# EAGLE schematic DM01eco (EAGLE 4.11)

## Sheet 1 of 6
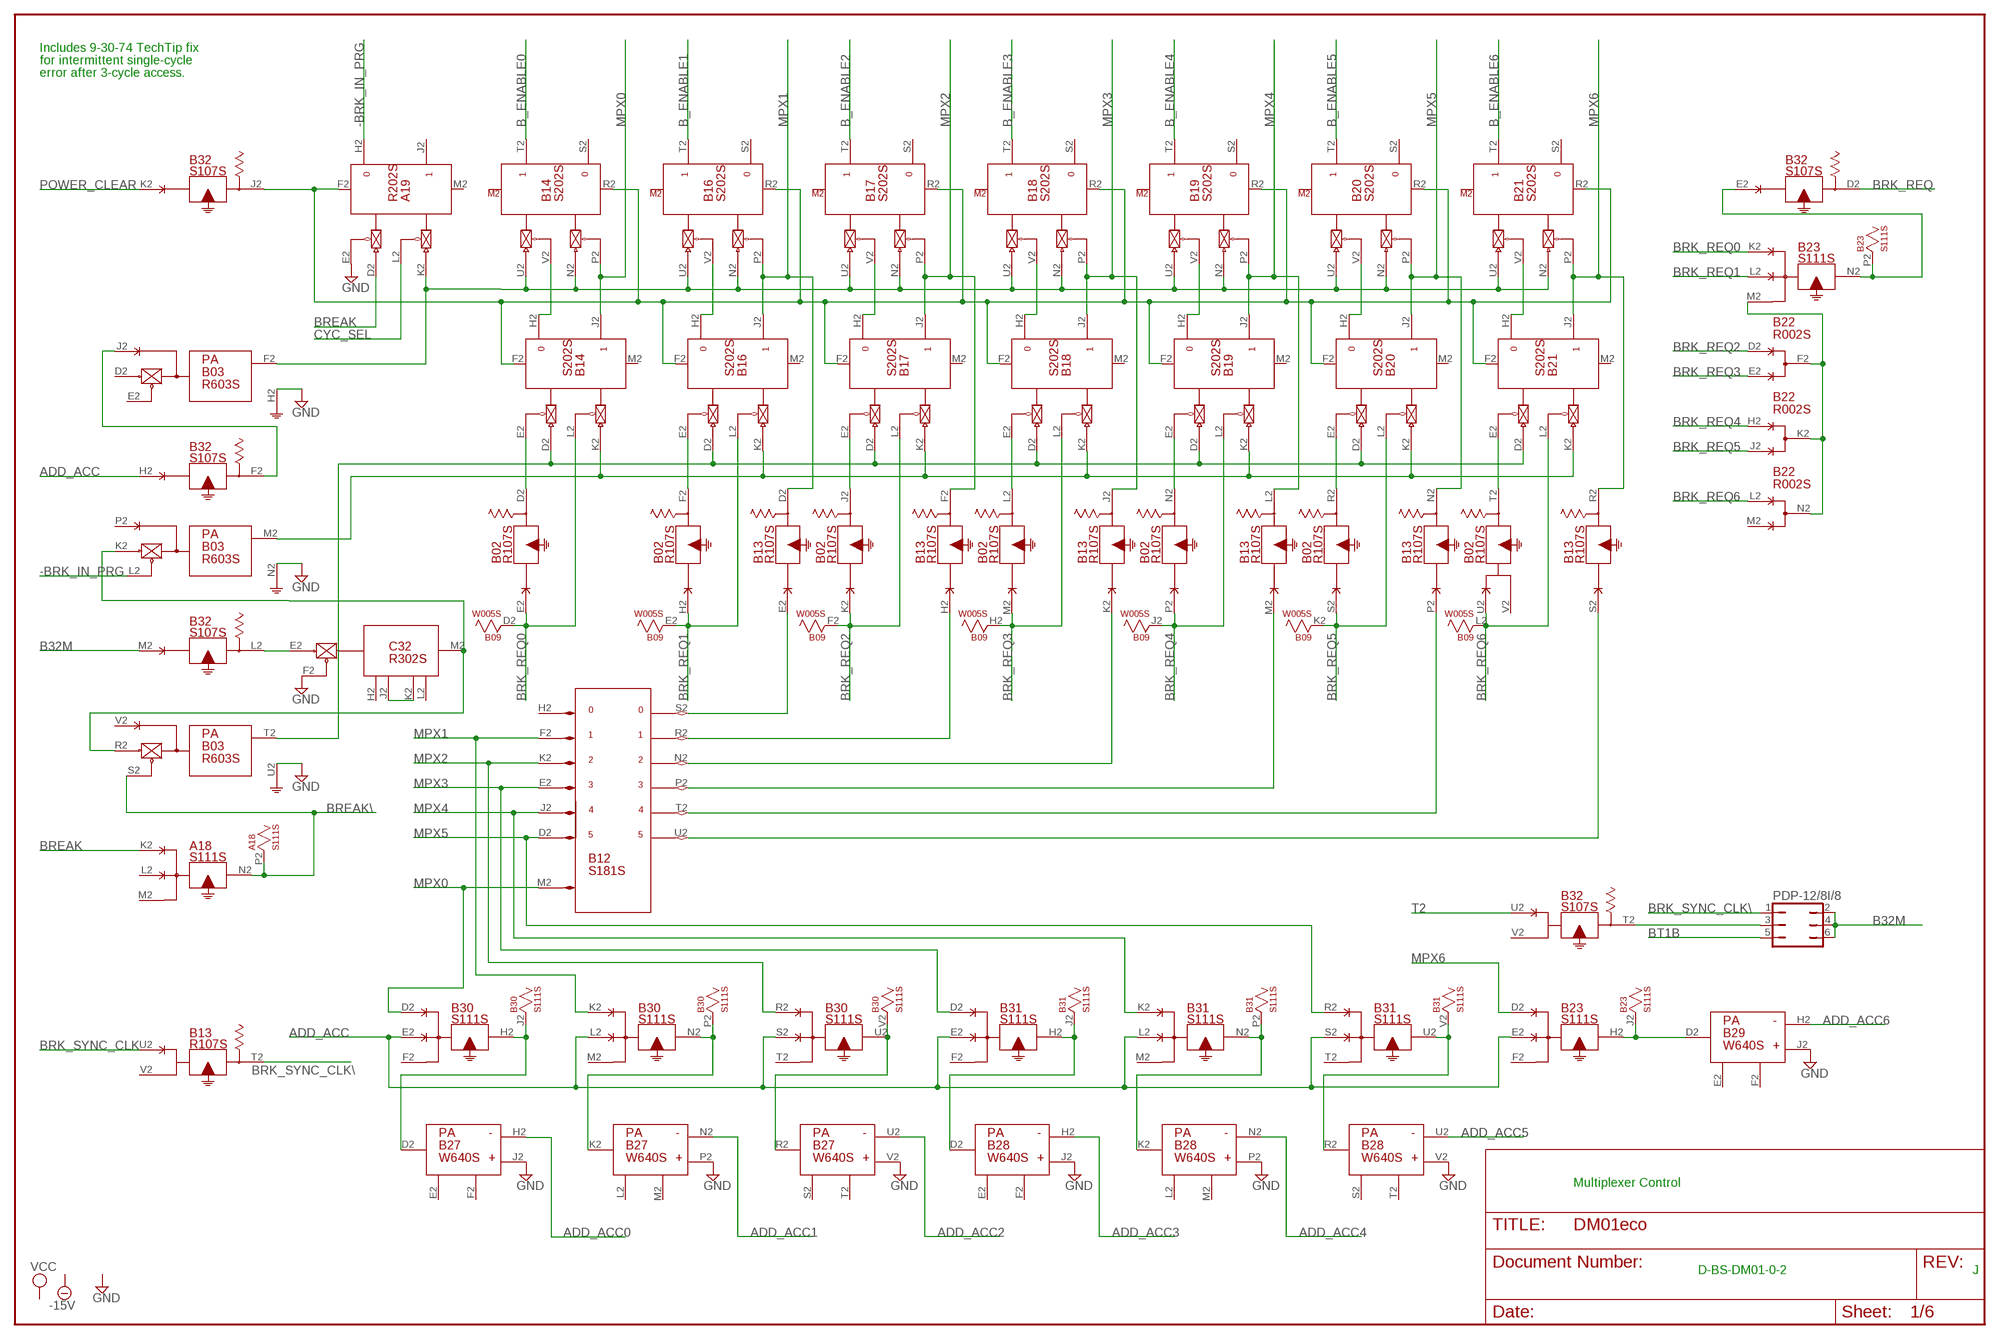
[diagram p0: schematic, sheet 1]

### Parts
A18  S111S  R111S  [H807S]
A19  R202S  [H807S]
B02  R107S  [H807S]
B03  R603S  [H807S]
B09  W005S  [H807S]
B12  S181S  R181S  [H807S]
B13  R107S  [H807S]
B14  S202S  R202S  [H807S]
B16  S202S  R202S  [H807S]
B17  S202S  R202S  [H807S]
B18  S202S  R202S  [H807S]
B19  S202S  R202S  [H807S]
B20  S202S  R202S  [H807S]
B21  S202S  R202S  [H807S]
B22  R002S  [H807S]
B23  S111S  R111S  [H807S]
B27  W640S  [H807S]
B28  W640S  [H807S]
B29  W640S  [H807S]
B30  S111S  R111S  [H807S]
B31  S111S  R111S  [H807S]
B32  S107S  R107S  [H807S]
C32  R302S  [H807S]
PDP-12/8I/8  JP3Q  [JP3Q]

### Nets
-BRK_IN_PRG: A19.H2 B03.L2(M:EN0)
ADD_ACC: B23.E2(H:I$2) B30.E2(H:I$2) B30.L2(N:I$2) B30.S2(U:I$2) B31.E2(H:I$2) B31.L2(N:I$2) B31.S2(U:I$2) B32.H2(F:I$1) ; also sheet 2
ADD_ACC0: B27.H2(H) ; also sheet 2
ADD_ACC1: B27.N2(H) ; also sheet 2
ADD_ACC2: B27.U2(H) ; also sheet 2
ADD_ACC3: B28.H2(H) ; also sheet 2
ADD_ACC4: B28.N2(H) ; also sheet 2
ADD_ACC5: B28.U2(H) ; also sheet 2
ADD_ACC6: B29.H2(H) ; also sheet 2
B32M: B32.M2(L:I$1) PDP-12/8I/8.2 PDP-12/8I/8.4 PDP-12/8I/8.6
B_ENABLE0: B14.T2 ; also sheet 2,4
B_ENABLE1: B16.T2 ; also sheet 2,4
B_ENABLE2: B17.T2 ; also sheet 2,4
B_ENABLE3: B18.T2 ; also sheet 2,4
B_ENABLE4: B19.T2 ; also sheet 2,4
B_ENABLE5: B20.T2 ; also sheet 2,4
B_ENABLE6: B21.T2 ; also sheet 2,4
BREAK: A18.K2(N:I$1) A19.D2(J:PU0) ; also sheet 2,4
BREAK\: A18.N2(N:O$1) A18.P2 B03.S2(T:EN0)
BRK_REQ: B32.D2(D:O$1) ; also sheet 2
BRK_REQ0: B02.E2(D:I$1) B09.D2 B14.L2(J:EN1) B23.K2(N:I$1) ; also sheet 2
BRK_REQ1: B02.H2(F:I$1) B09.E2 B16.L2(J:EN1) B23.L2(N:I$2) ; also sheet 2
BRK_REQ2: B02.K2(J:I$1) B09.F2 B17.L2(J:EN1) B22.D2(F:D) ; also sheet 2
BRK_REQ3: B02.M2(L:I$1) B09.H2 B18.L2(J:EN1) B22.E2(F:E) ; also sheet 2
BRK_REQ4: B02.P2(N:I$1) B09.J2 B19.L2(J:EN1) B22.H2(K:D) ; also sheet 2
BRK_REQ5: B02.S2(R:I$1) B09.K2 B20.L2(J:EN1) B22.J2(K:E) ; also sheet 2
BRK_REQ6: B02.U2(T:I$1) B09.L2 B21.L2(J:EN1) B22.L2(N:D) ; also sheet 2
BRK_SYNC_CLK: B13.U2(T:I$1) ; also sheet 3
BRK_SYNC_CLK\: B13.T2(T:O$1) PDP-12/8I/8.1
BT1B: PDP-12/8I/8.5 ; also sheet 3
CYC_SEL: A19.L2(J:EN1) ; also sheet 2,5
GND [Supply]: A19.E2(J:EN0) B03.H2(F:G) B03.N2(M:G) B03.U2(T:G) B27.J2(J) B27.P2(J) B27.V2(J) B28.J2(J) B28.P2(J) B28.V2(J) B29.J2(J) C32.F2(M:F) ; also sheet 4
MPX0: B12.M2(M) B14.J2 B14.P2(T:EN0) B30.D2(H:I$1) ; also sheet 2,4
MPX1: B12.F2(F) B13.D2(D:O$1) B16.J2 B16.P2(T:EN0) B30.K2(N:I$1) ; also sheet 2,4
MPX2: B12.K2(K) B13.F2(F:O$1) B17.J2 B17.P2(T:EN0) B30.R2(U:I$1) ; also sheet 2,4
MPX3: B12.E2(E) B13.J2(J:O$1) B18.J2 B18.P2(T:EN0) B31.D2(H:I$1) ; also sheet 2,4
MPX4: B12.J2(J) B13.L2(L:O$1) B19.J2 B19.P2(T:EN0) B31.K2(N:I$1) ; also sheet 2,4
MPX5: B12.D2(D) B13.N2(N:O$1) B20.J2 B20.P2(T:EN0) B31.R2(U:I$1) ; also sheet 2,4
MPX6: B13.R2(R:O$1) B21.J2 B21.P2(T:EN0) B23.D2(H:I$1) ; also sheet 2,4
N$1: A19.K2(J:PU1) B03.F2(F:O) B14.N2(T:PU0) B14.U2(T:PU1) B16.N2(T:PU0) B16.U2(T:PU1) B17.N2(T:PU0) B17.U2(T:PU1) B18.N2(T:PU0) B18.U2(T:PU1) B19.N2(T:PU0) B19.U2(T:PU1) B20.N2(T:PU0) B20.U2(T:PU1) B21.N2(T:PU0) B21.U2(T:PU1)
N$2: A19.F2(J:RESET) B14.F2(J:RESET) B14.R2(T:RESET) B16.F2(J:RESET) B16.R2(T:RESET) B17.F2(J:RESET) B17.R2(T:RESET) B18.F2(J:RESET) B18.R2(T:RESET) B19.F2(J:RESET) B19.R2(T:RESET) B20.F2(J:RESET) B20.R2(T:RESET) B21.F2(J:RESET) B21.R2(T:RESET) B32.J2(J:O$1)
N$3: B03.J2(F:I$1) B32.F2(F:O$1)
N$4: B32.T2(T:O$1) PDP-12/8I/8.3
N$5: B03.K2(M:PU0) B03.R2(T:PU0) C32.M2(M:M)
N$6: B03.M2(M:O) B14.K2(J:PU1) B16.K2(J:PU1) B17.K2(J:PU1) B18.K2(J:PU1) B19.K2(J:PU1) B20.K2(J:PU1) B21.K2(J:PU1)
N$7: B14.H2 B14.V2(T:EN1)
N$8: C32.J2(M:J) C32.K2(M:K)
N$9: B16.H2 B16.V2(T:EN1)
N$10: B32.L2(L:O$1) C32.E2(M:E)
N$11: B17.H2 B17.V2(T:EN1)
N$13: B18.H2 B18.V2(T:EN1)
N$15: B19.H2 B19.V2(T:EN1)
N$17: B20.H2 B20.V2(T:EN1)
N$19: B21.H2 B21.V2(T:EN1)
N$21: B23.N2(N:O$1) B23.P2 B32.E2(D:I$1)
N$22: B22.F2(F:F) B22.K2(K:F) B22.N2(N:F) B23.M2(N:I$3)
N$23: B02.D2(D:O$1) B14.E2(J:EN0)
N$24: B02.F2(F:O$1) B16.E2(J:EN0)
N$25: B02.J2(J:O$1) B17.E2(J:EN0)
N$26: B02.L2(L:O$1) B18.E2(J:EN0)
N$27: B02.N2(N:O$1) B19.E2(J:EN0)
N$28: B02.R2(R:O$1) B20.E2(J:EN0)
N$29: B02.T2(T:O$1) B21.E2(J:EN0)
N$30: B27.D2(D) B30.H2(H:O$1) B30.J2
N$32: B03.T2(T:O) B14.D2(J:PU0) B16.D2(J:PU0) B17.D2(J:PU0) B18.D2(J:PU0) B19.D2(J:PU0) B20.D2(J:PU0) B21.D2(J:PU0)
N$36: B27.K2(D) B30.N2(N:O$1) B30.P2
N$37: B27.R2(D) B30.U2(U:O$1) B30.V2
N$38: B12.S2(S) B13.E2(D:I$1)
N$39: B12.R2(R) B13.H2(F:I$1)
N$40: B12.N2(N) B13.K2(J:I$1)
N$41: B12.P2(P) B13.M2(L:I$1)
N$42: B12.T2(T) B13.P2(N:I$1)
N$43: B12.U2(U) B13.S2(R:I$1)
N$45: B28.D2(D) B31.H2(H:O$1) B31.J2
N$46: B28.K2(D) B31.N2(N:O$1) B31.P2
N$47: B28.R2(D) B31.U2(U:O$1) B31.V2
N$48: B23.H2(H:O$1) B23.J2 B29.D2(D)
POWER_CLEAR: B32.K2(J:I$1) ; also sheet 3
T2: B32.U2(T:I$1) ; also sheet 3
Unconnected: A18.R2(U:I$1) A18.S2(U:I$2) A18.T2(U:I$3) A18.U2(U:O$1) A18.V2 A19.J2 A19.M2(J:SET) A19.N2(T:PU0) A19.P2(T:EN0) A19.R2(T:RESET) A19.S2 A19.T2 A19.U2(T:PU1) A19.V2(T:EN1) B02.V2(T:I$2) B03.D2(F:PU0) B03.E2(F:EN0) B03.P2(M:I$1) B03.V2(T:I$1) B09.U2 B12.H2(H) B12.L2(I$1) B12.V2(O$1) B13.V2(T:I$2) B14.M2(J:SET) B14.S2 B16.M2(J:SET) B16.S2 B17.M2(J:SET) B17.S2 B18.M2(J:SET) B18.S2 B19.M2(J:SET) B19.S2 B20.M2(J:SET) B20.S2 B21.M2(J:SET) B21.S2 B22.M2(N:E) B22.P2(S:D) B22.R2(S:E) B22.S2(S:F) B22.T2(V:D) B22.U2(V:E) B22.V2(V:F) B27.E2(E) B27.F2(F) B27.L2(E) B27.M2(F) B27.S2(E) B27.T2(F) B28.E2(E) B28.F2(F) B28.L2(E) B28.M2(F) B28.S2(E) B28.T2(F) B30.F2(H:I$3) B30.M2(N:I$3) B30.T2(U:I$3) B31.F2(H:I$3) B31.M2(N:I$3) B31.T2(U:I$3) C32.H2(M:H) C32.L2(M:L) C32.N2(V:E) C32.P2(V:F) C32.R2(V:H) C32.S2(V:J) C32.T2(V:K) C32.U2(V:L) C32.V2(V:M)

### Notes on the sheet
- Includes 9-30-74 TechTip fix
- for intermittent single-cycle
- error after 3-cycle access.
- Multiplexer Control
- D-BS-DM01-0-2 | J

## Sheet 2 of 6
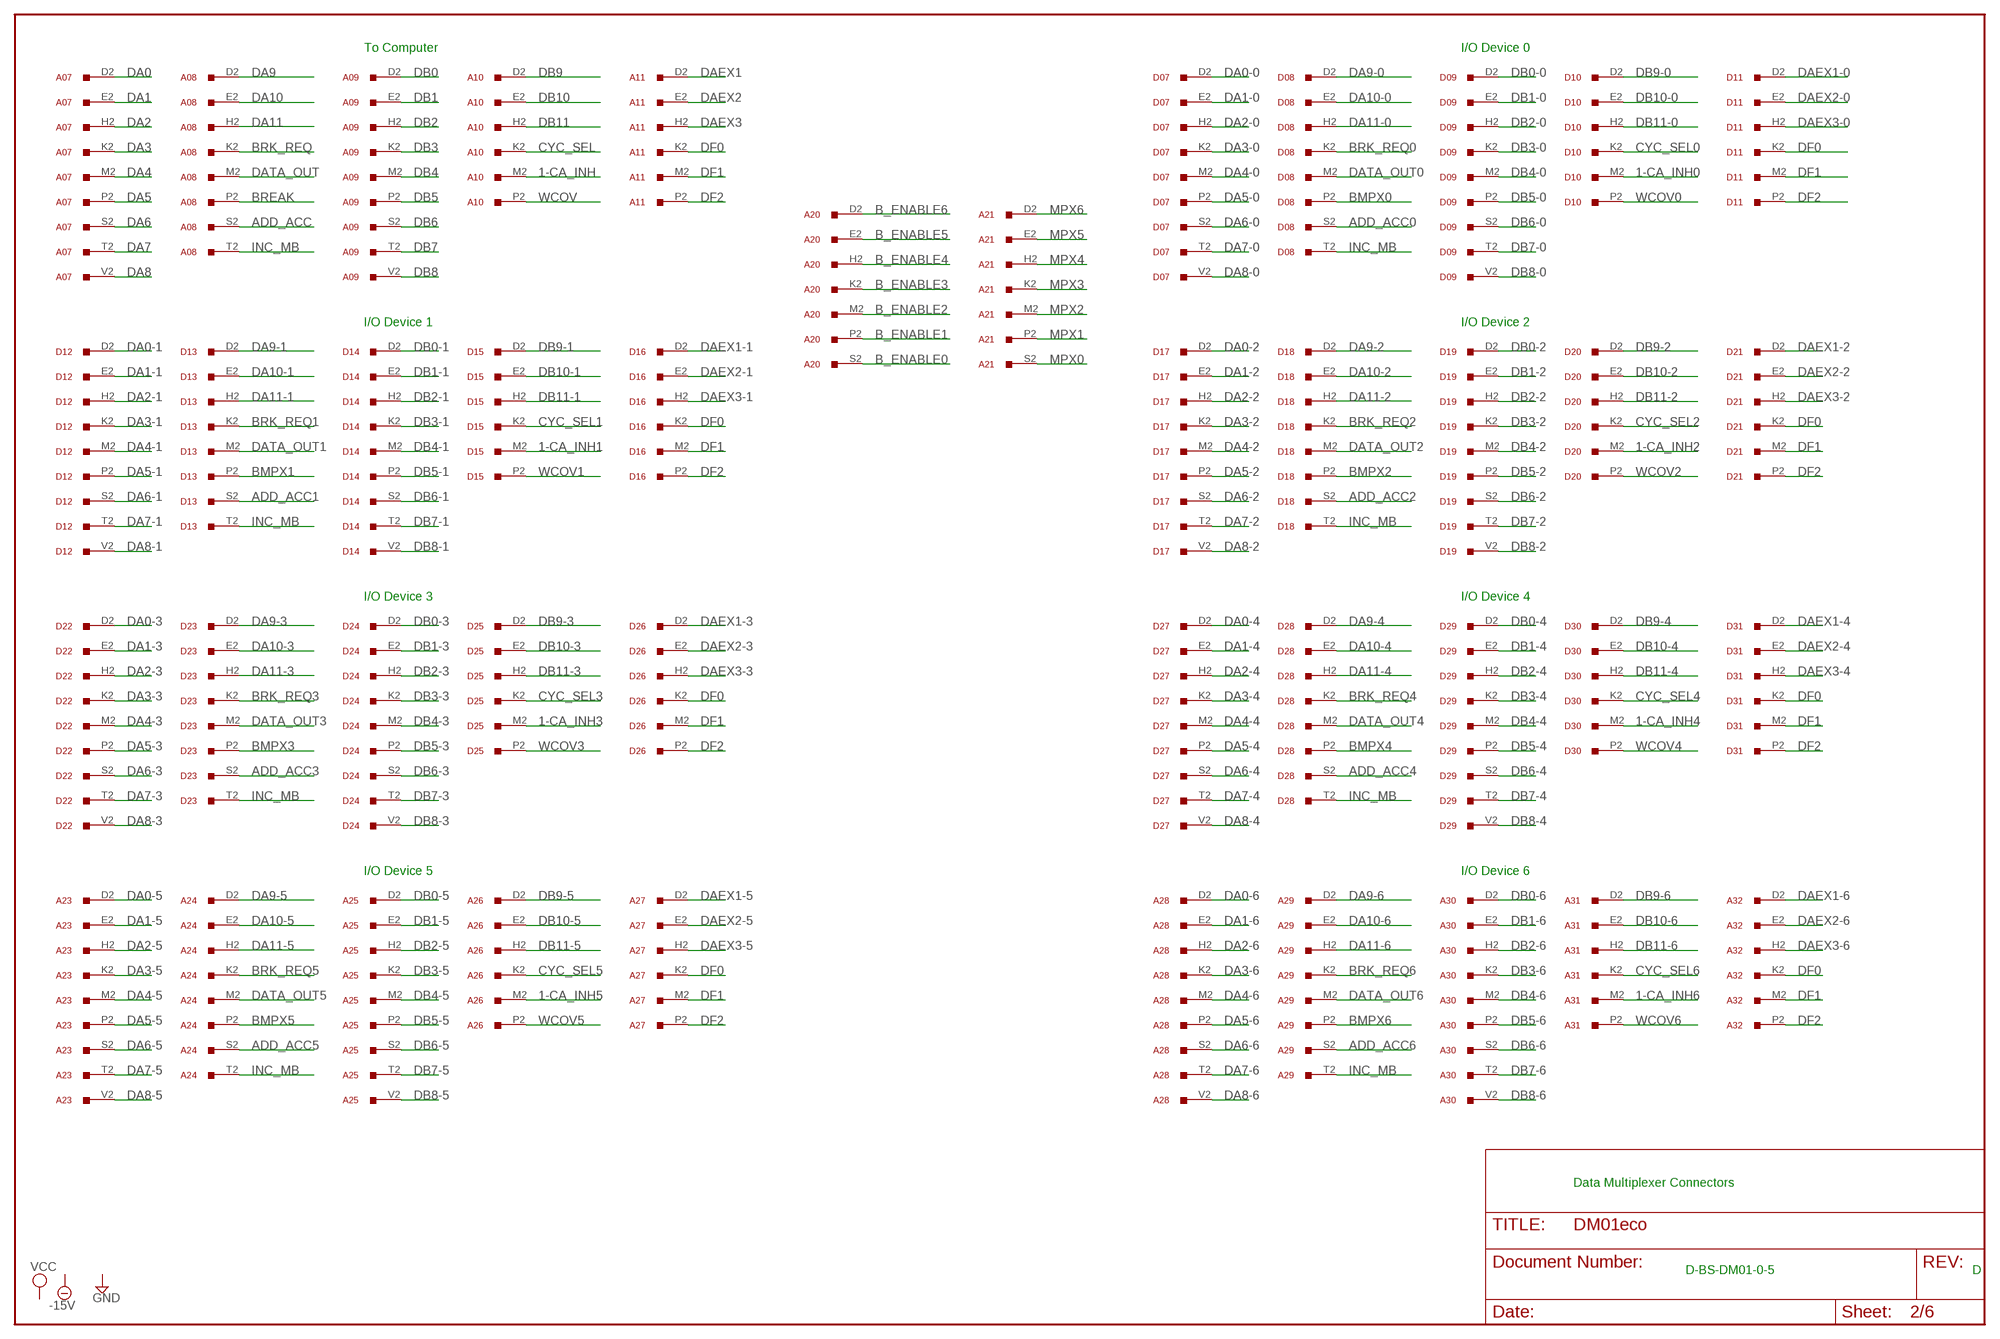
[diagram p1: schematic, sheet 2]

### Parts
A07  W021S  [H807S]
A08  W021S  [H807S]
A09  W021S  [H807S]
A10  W021S  [H807S]
A11  W021S  [H807S]
A20  W021S  [H807S]
A21  W021S  [H807S]
A23  W021S  [H807S]
A24  W021S  [H807S]
A25  W021S  [H807S]
A26  W021S  [H807S]
A27  W021S  [H807S]
A28  W021S  [H807S]
A29  W021S  [H807S]
A30  W021S  [H807S]
A31  W021S  [H807S]
A32  W021S  [H807S]
D07  W021S  [H807S]
D08  W021S  [H807S]
D09  W021S  [H807S]
D10  W021S  [H807S]
D11  W021S  [H807S]
D12  W021S  [H807S]
D13  W021S  [H807S]
D14  W021S  [H807S]
D15  W021S  [H807S]
D16  W021S  [H807S]
D17  W021S  [H807S]
D18  W021S  [H807S]
D19  W021S  [H807S]
D20  W021S  [H807S]
D21  W021S  [H807S]
D22  W021S  [H807S]
D23  W021S  [H807S]
D24  W021S  [H807S]
D25  W021S  [H807S]
D26  W021S  [H807S]
D27  W021S  [H807S]
D28  W021S  [H807S]
D29  W021S  [H807S]
D30  W021S  [H807S]
D31  W021S  [H807S]

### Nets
1-CA_INH: A10.M2 ; also sheet 6
1-CA_INH0: D10.M2 ; also sheet 6
1-CA_INH1: D15.M2 ; also sheet 6
1-CA_INH2: D20.M2 ; also sheet 6
1-CA_INH3: D25.M2 ; also sheet 6
1-CA_INH4: D30.M2 ; also sheet 6
1-CA_INH5: A26.M2 ; also sheet 6
1-CA_INH6: A31.M2 ; also sheet 6
ADD_ACC: A08.S2 ; also sheet 1
ADD_ACC0: D08.S2 ; also sheet 1
ADD_ACC1: D13.S2 ; also sheet 1
ADD_ACC2: D18.S2 ; also sheet 1
ADD_ACC3: D23.S2 ; also sheet 1
ADD_ACC4: D28.S2 ; also sheet 1
ADD_ACC5: A24.S2 ; also sheet 1
ADD_ACC6: A29.S2 ; also sheet 1
B_ENABLE0: A20.S2 ; also sheet 1,4
B_ENABLE1: A20.P2 ; also sheet 1,4
B_ENABLE2: A20.M2 ; also sheet 1,4
B_ENABLE3: A20.K2 ; also sheet 1,4
B_ENABLE4: A20.H2 ; also sheet 1,4
B_ENABLE5: A20.E2 ; also sheet 1,4
B_ENABLE6: A20.D2 ; also sheet 1,4
BMPX0: D08.P2 ; also sheet 4
BMPX1: D13.P2 ; also sheet 4
BMPX2: D18.P2 ; also sheet 4
BMPX3: D23.P2 ; also sheet 4
BMPX4: D28.P2 ; also sheet 4
BMPX5: A24.P2 ; also sheet 4
BMPX6: A29.P2 ; also sheet 4
BREAK: A08.P2 ; also sheet 1,4
BRK_REQ: A08.K2 ; also sheet 1
BRK_REQ0: D08.K2 ; also sheet 1
BRK_REQ1: D13.K2 ; also sheet 1
BRK_REQ2: D18.K2 ; also sheet 1
BRK_REQ3: D23.K2 ; also sheet 1
BRK_REQ4: D28.K2 ; also sheet 1
BRK_REQ5: A24.K2 ; also sheet 1
BRK_REQ6: A29.K2 ; also sheet 1
CYC_SEL: A10.K2 ; also sheet 1,5
CYC_SEL0: D10.K2 ; also sheet 5
CYC_SEL1: D15.K2 ; also sheet 5
CYC_SEL2: D20.K2 ; also sheet 5
CYC_SEL3: D25.K2 ; also sheet 5
CYC_SEL4: D30.K2 ; also sheet 5
CYC_SEL5: A26.K2 ; also sheet 5
CYC_SEL6: A31.K2 ; also sheet 5
DA0: A07.D2 ; also sheet 5
DA0-0: D07.D2 ; also sheet 5
DA0-1: D12.D2 ; also sheet 5
DA0-2: D17.D2 ; also sheet 5
DA0-3: D22.D2 ; also sheet 5
DA0-4: D27.D2 ; also sheet 5
DA0-5: A23.D2 ; also sheet 5
DA0-6: A28.D2 ; also sheet 5
DA1: A07.E2 ; also sheet 5
DA1-0: D07.E2 ; also sheet 5
DA1-1: D12.E2 ; also sheet 5
DA1-2: D17.E2 ; also sheet 5
DA1-3: D22.E2 ; also sheet 5
DA1-4: D27.E2 ; also sheet 5
DA1-5: A23.E2 ; also sheet 5
DA1-6: A28.E2 ; also sheet 5
DA2: A07.H2 ; also sheet 5
DA2-0: D07.H2 ; also sheet 5
DA2-1: D12.H2 ; also sheet 5
DA2-2: D17.H2 ; also sheet 5
DA2-3: D22.H2 ; also sheet 5
DA2-4: D27.H2 ; also sheet 5
DA2-5: A23.H2 ; also sheet 5
DA2-6: A28.H2 ; also sheet 5
DA3: A07.K2 ; also sheet 5
DA3-0: D07.K2 ; also sheet 5
DA3-1: D12.K2 ; also sheet 5
DA3-2: D17.K2 ; also sheet 5
DA3-3: D22.K2 ; also sheet 5
DA3-4: D27.K2 ; also sheet 5
DA3-5: A23.K2 ; also sheet 5
DA3-6: A28.K2 ; also sheet 5
DA4: A07.M2 ; also sheet 5
DA4-0: D07.M2 ; also sheet 5
DA4-1: D12.M2 ; also sheet 5
DA4-2: D17.M2 ; also sheet 5
DA4-3: D22.M2 ; also sheet 5
DA4-4: D27.M2 ; also sheet 5
DA4-5: A23.M2 ; also sheet 5
DA4-6: A28.M2 ; also sheet 5
DA5: A07.P2 ; also sheet 5
DA5-0: D07.P2 ; also sheet 5
DA5-1: D12.P2 ; also sheet 5
DA5-2: D17.P2 ; also sheet 5
DA5-3: D22.P2 ; also sheet 5
DA5-4: D27.P2 ; also sheet 5
DA5-5: A23.P2 ; also sheet 5
DA5-6: A28.P2 ; also sheet 5
DA6: A07.S2 ; also sheet 5
DA6-0: D07.S2 ; also sheet 5
DA6-1: D12.S2 ; also sheet 5
DA6-2: D17.S2 ; also sheet 5
DA6-3: D22.S2 ; also sheet 5
DA6-4: D27.S2 ; also sheet 5
DA6-5: A23.S2 ; also sheet 5
DA6-6: A28.S2 ; also sheet 5
DA7: A07.T2 ; also sheet 5
DA7-0: D07.T2 ; also sheet 5
DA7-1: D12.T2 ; also sheet 5
DA7-2: D17.T2 ; also sheet 5
DA7-3: D22.T2 ; also sheet 5
DA7-4: D27.T2 ; also sheet 5
DA7-5: A23.T2 ; also sheet 5
DA7-6: A28.T2 ; also sheet 5
DA8: A07.V2 ; also sheet 5
DA8-0: D07.V2 ; also sheet 5
DA8-1: D12.V2 ; also sheet 5
DA8-2: D17.V2 ; also sheet 5
DA8-3: D22.V2 ; also sheet 5
DA8-4: D27.V2 ; also sheet 5
DA8-5: A23.V2 ; also sheet 5
DA8-6: A28.V2 ; also sheet 5
DA9: A08.D2 ; also sheet 5
DA9-0: D08.D2 ; also sheet 5
DA9-1: D13.D2 ; also sheet 5
DA9-2: D18.D2 ; also sheet 5
DA9-3: D23.D2 ; also sheet 5
DA9-4: D28.D2 ; also sheet 5
DA9-5: A24.D2 ; also sheet 5
DA9-6: A29.D2 ; also sheet 5
DA10: A08.E2 ; also sheet 5
DA10-0: D08.E2 ; also sheet 5
DA10-1: D13.E2 ; also sheet 5
DA10-2: D18.E2 ; also sheet 5
DA10-3: D23.E2 ; also sheet 5
DA10-4: D28.E2 ; also sheet 5
DA10-5: A24.E2 ; also sheet 5
DA10-6: A29.E2 ; also sheet 5
DA11: A08.H2 ; also sheet 5
DA11-0: D08.H2 ; also sheet 5
DA11-1: D13.H2 ; also sheet 5
DA11-2: D18.H2 ; also sheet 5
DA11-3: D23.H2 ; also sheet 5
DA11-4: D28.H2 ; also sheet 5
DA11-5: A24.H2 ; also sheet 5
DA11-6: A29.H2 ; also sheet 5
DAEX1: A11.D2 ; also sheet 5
DAEX1-0: D11.D2 ; also sheet 5
DAEX1-1: D16.D2 ; also sheet 5
DAEX1-2: D21.D2 ; also sheet 5
DAEX1-3: D26.D2 ; also sheet 5
DAEX1-4: D31.D2 ; also sheet 5
DAEX1-5: A27.D2 ; also sheet 5
DAEX1-6: A32.D2 ; also sheet 5
DAEX2: A11.E2 ; also sheet 5
DAEX2-0: D11.E2 ; also sheet 5
DAEX2-1: D16.E2 ; also sheet 5
DAEX2-2: D21.E2 ; also sheet 5
DAEX2-3: D26.E2 ; also sheet 5
DAEX2-4: D31.E2 ; also sheet 5
DAEX2-5: A27.E2 ; also sheet 5
DAEX2-6: A32.E2 ; also sheet 5
DAEX3: A11.H2 ; also sheet 5
DAEX3-0: D11.H2 ; also sheet 5
DAEX3-1: D16.H2 ; also sheet 5
DAEX3-2: D21.H2 ; also sheet 5
DAEX3-3: D26.H2 ; also sheet 5
DAEX3-4: D31.H2 ; also sheet 5
DAEX3-5: A27.H2 ; also sheet 5
DAEX3-6: A32.H2 ; also sheet 5
DATA_OUT: A08.M2 ; also sheet 6
DATA_OUT0: D08.M2 ; also sheet 6
DATA_OUT1: D13.M2 ; also sheet 6
DATA_OUT2: D18.M2 ; also sheet 6
DATA_OUT3: D23.M2 ; also sheet 6
DATA_OUT4: D28.M2 ; also sheet 6
DATA_OUT5: A24.M2 ; also sheet 6
DATA_OUT6: A29.M2 ; also sheet 6
DB0: A09.D2 ; also sheet 6
DB0-0: D09.D2 ; also sheet 6
DB0-1: D14.D2 ; also sheet 6
DB0-2: D19.D2 ; also sheet 6
DB0-3: D24.D2 ; also sheet 6
DB0-4: D29.D2 ; also sheet 6
DB0-5: A25.D2 ; also sheet 6
DB0-6: A30.D2 ; also sheet 6
DB1: A09.E2 ; also sheet 6
DB1-0: D09.E2 ; also sheet 6
DB1-1: D14.E2 ; also sheet 6
DB1-2: D19.E2 ; also sheet 6
DB1-3: D24.E2 ; also sheet 6
DB1-4: D29.E2 ; also sheet 6
DB1-5: A25.E2 ; also sheet 6
DB1-6: A30.E2 ; also sheet 6
DB2: A09.H2 ; also sheet 6
DB2-0: D09.H2 ; also sheet 6
DB2-1: D14.H2 ; also sheet 6
DB2-2: D19.H2 ; also sheet 6
DB2-3: D24.H2 ; also sheet 6
DB2-4: D29.H2 ; also sheet 6
DB2-5: A25.H2 ; also sheet 6
DB2-6: A30.H2 ; also sheet 6
DB3: A09.K2 ; also sheet 6
DB3-0: D09.K2 ; also sheet 6
DB3-1: D14.K2 ; also sheet 6
DB3-2: D19.K2 ; also sheet 6
DB3-3: D24.K2 ; also sheet 6
DB3-4: D29.K2 ; also sheet 6
DB3-5: A25.K2 ; also sheet 6
DB3-6: A30.K2 ; also sheet 6
DB4: A09.M2 ; also sheet 6
DB4-0: D09.M2 ; also sheet 6
DB4-1: D14.M2 ; also sheet 6
DB4-2: D19.M2 ; also sheet 6
DB4-3: D24.M2 ; also sheet 6
DB4-4: D29.M2 ; also sheet 6
DB4-5: A25.M2 ; also sheet 6
DB4-6: A30.M2 ; also sheet 6
DB5: A09.P2 ; also sheet 6
DB5-0: D09.P2 ; also sheet 6
DB5-1: D14.P2 ; also sheet 6
DB5-2: D19.P2 ; also sheet 6
DB5-3: D24.P2 ; also sheet 6
DB5-4: D29.P2 ; also sheet 6
DB5-5: A25.P2 ; also sheet 6
DB5-6: A30.P2 ; also sheet 6
DB6: A09.S2 ; also sheet 6
DB6-0: D09.S2 ; also sheet 6
DB6-1: D14.S2 ; also sheet 6
DB6-2: D19.S2 ; also sheet 6
DB6-3: D24.S2 ; also sheet 6
DB6-4: D29.S2 ; also sheet 6
DB6-5: A25.S2 ; also sheet 6
DB6-6: A30.S2 ; also sheet 6
DB7: A09.T2 ; also sheet 6
DB7-0: D09.T2 ; also sheet 6
DB7-1: D14.T2 ; also sheet 6
DB7-2: D19.T2 ; also sheet 6
DB7-3: D24.T2 ; also sheet 6
DB7-4: D29.T2 ; also sheet 6
DB7-5: A25.T2 ; also sheet 6
DB7-6: A30.T2 ; also sheet 6
DB8: A09.V2 ; also sheet 6
DB8-0: D09.V2 ; also sheet 6
DB8-1: D14.V2 ; also sheet 6
DB8-2: D19.V2 ; also sheet 6
DB8-3: D24.V2 ; also sheet 6
DB8-4: D29.V2 ; also sheet 6
DB8-5: A25.V2 ; also sheet 6
DB8-6: A30.V2 ; also sheet 6
DB9: A10.D2 ; also sheet 6
DB9-0: D10.D2 ; also sheet 6
DB9-1: D15.D2 ; also sheet 6
DB9-2: D20.D2 ; also sheet 6
DB9-3: D25.D2 ; also sheet 6
DB9-4: D30.D2 ; also sheet 6
DB9-5: A26.D2 ; also sheet 6
DB9-6: A31.D2 ; also sheet 6
DB10: A10.E2 ; also sheet 6
DB10-0: D10.E2 ; also sheet 6
DB10-1: D15.E2 ; also sheet 6
DB10-2: D20.E2 ; also sheet 6
DB10-3: D25.E2 ; also sheet 6
DB10-4: D30.E2 ; also sheet 6
DB10-5: A26.E2 ; also sheet 6
DB10-6: A31.E2 ; also sheet 6
DB11: A10.H2 ; also sheet 6
DB11-0: D10.H2 ; also sheet 6
DB11-1: D15.H2 ; also sheet 6
DB11-2: D20.H2 ; also sheet 6
DB11-3: D25.H2 ; also sheet 6
DB11-4: D30.H2 ; also sheet 6
DB11-5: A26.H2 ; also sheet 6
DB11-6: A31.H2 ; also sheet 6
DF0: A11.K2 A27.K2 A32.K2 D11.K2 D16.K2 D21.K2 D26.K2 D31.K2
DF1: A11.M2 A27.M2 A32.M2 D11.M2 D16.M2 D21.M2 D26.M2 D31.M2
DF2: A11.P2 A27.P2 A32.P2 D11.P2 D16.P2 D21.P2 D26.P2 D31.P2
INC_MB: A08.T2 A24.T2 A29.T2 D08.T2 D13.T2 D18.T2 D23.T2 D28.T2
MPX0: A21.S2 ; also sheet 1,4
MPX1: A21.P2 ; also sheet 1,4
MPX2: A21.M2 ; also sheet 1,4
MPX3: A21.K2 ; also sheet 1,4
MPX4: A21.H2 ; also sheet 1,4
MPX5: A21.E2 ; also sheet 1,4
MPX6: A21.D2 ; also sheet 1,4
WCOV: A10.P2 ; also sheet 4
WCOV0: D10.P2 ; also sheet 4
WCOV1: D15.P2 ; also sheet 4
WCOV2: D20.P2 ; also sheet 4
WCOV3: D25.P2 ; also sheet 4
WCOV4: D30.P2 ; also sheet 4
WCOV5: A26.P2 ; also sheet 4
WCOV6: A31.P2 ; also sheet 4
Unconnected: A08.V2 A10.S2 A10.T2 A10.V2 A11.S2 A11.T2 A11.V2 A20.T2 A20.V2 A21.T2 A21.V2 A24.V2 A26.S2 A26.T2 A26.V2 A27.S2 A27.T2 A27.V2 A29.V2 A31.S2 A31.T2 A31.V2 A32.S2 A32.T2 A32.V2 D08.V2 D10.S2 D10.T2 D10.V2 D11.S2 D11.T2 D11.V2 D13.V2 D15.S2 D15.T2 D15.V2 D16.S2 D16.T2 D16.V2 D18.V2 D20.S2 D20.T2 D20.V2 D21.S2 D21.T2 D21.V2 D23.V2 D25.S2 D25.T2 D25.V2 D26.S2 D26.T2 D26.V2 D28.V2 D30.S2 D30.T2 D30.V2 D31.S2 D31.T2 D31.V2

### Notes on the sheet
- To Computer | I/O Device 0
- I/O Device 1 | I/O Device 2
- I/O Device 3 | I/O Device 4
- I/O Device 5 | I/O Device 6
- Data Multiplexer Connectors
- D-BS-DM01-0-5 | D

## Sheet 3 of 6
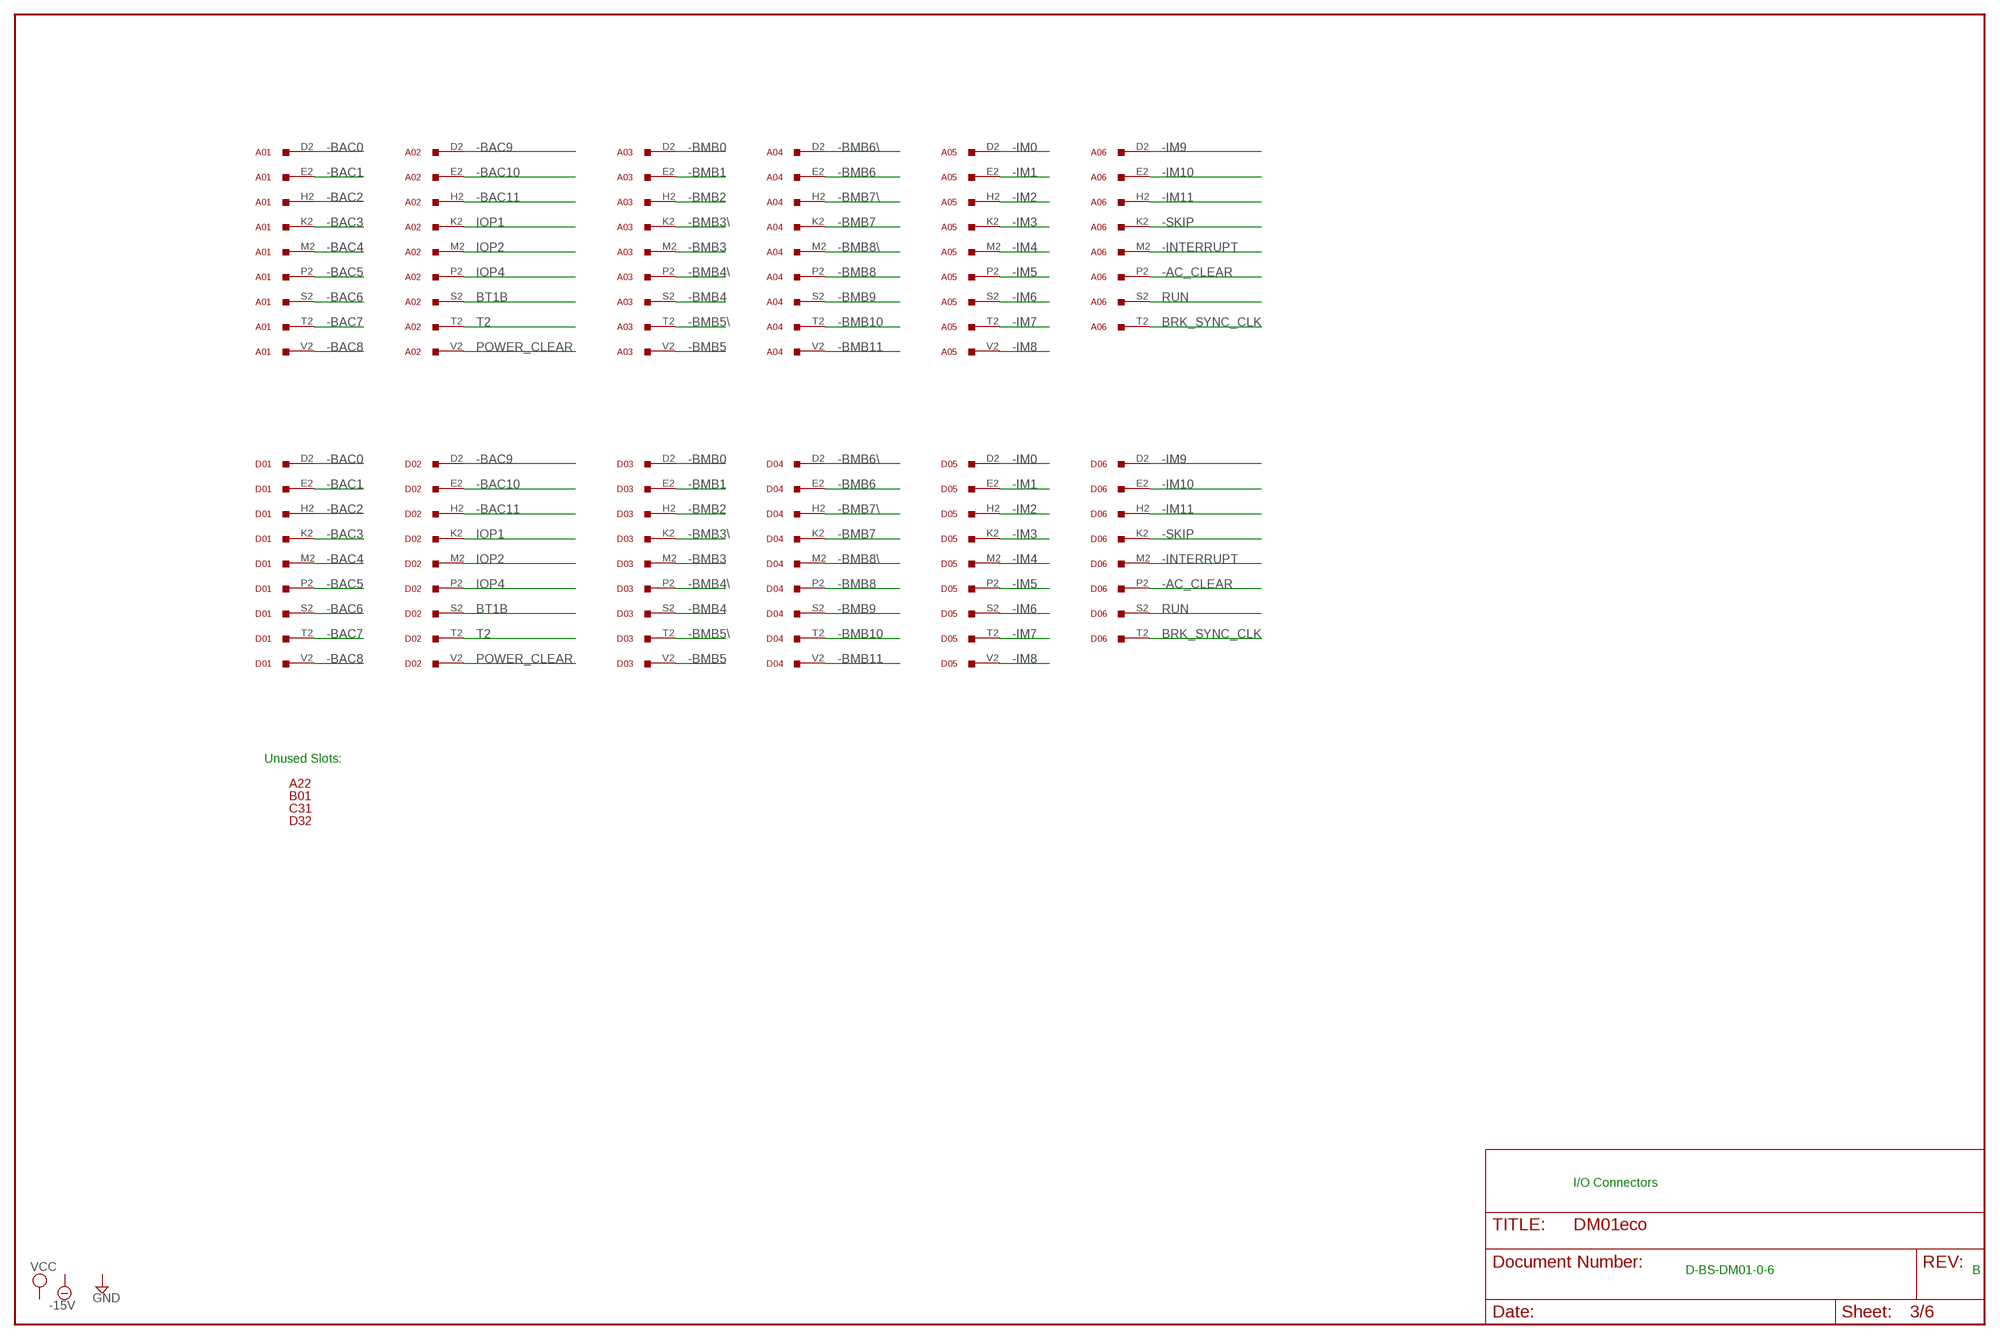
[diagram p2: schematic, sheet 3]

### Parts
A01  W021S  [H807S]
A02  W021S  [H807S]
A03  W021S  [H807S]
A04  W021S  [H807S]
A05  W021S  [H807S]
A06  W021S  [H807S]
A22  EMPTYS  [H807S]
B01  EMPTYS  [H807S]
C31  EMPTYS  [H807S]
D01  W021S  [H807S]
D02  W021S  [H807S]
D03  W021S  [H807S]
D04  W021S  [H807S]
D05  W021S  [H807S]
D06  W021S  [H807S]
D32  EMPTYS  [H807S]

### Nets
-AC_CLEAR: A06.P2 D06.P2
-BAC0: A01.D2 D01.D2
-BAC1: A01.E2 D01.E2
-BAC2: A01.H2 D01.H2
-BAC3: A01.K2 D01.K2
-BAC4: A01.M2 D01.M2
-BAC5: A01.P2 D01.P2
-BAC6: A01.S2 D01.S2
-BAC7: A01.T2 D01.T2
-BAC8: A01.V2 D01.V2
-BAC9: A02.D2 D02.D2
-BAC10: A02.E2 D02.E2
-BAC11: A02.H2 D02.H2
-BMB0: A03.D2 D03.D2
-BMB1: A03.E2 D03.E2
-BMB2: A03.H2 D03.H2
-BMB3: A03.M2 D03.M2
-BMB3\: A03.K2 D03.K2
-BMB4: A03.S2 D03.S2
-BMB4\: A03.P2 D03.P2
-BMB5: A03.V2 D03.V2
-BMB5\: A03.T2 D03.T2
-BMB6: A04.E2 D04.E2
-BMB6\: A04.D2 D04.D2
-BMB7: A04.K2 D04.K2
-BMB7\: A04.H2 D04.H2
-BMB8: A04.P2 D04.P2
-BMB8\: A04.M2 D04.M2
-BMB9: A04.S2 D04.S2
-BMB10: A04.T2 D04.T2
-BMB11: A04.V2 D04.V2
-IM0: A05.D2 D05.D2
-IM1: A05.E2 D05.E2
-IM2: A05.H2 D05.H2
-IM3: A05.K2 D05.K2
-IM4: A05.M2 D05.M2
-IM5: A05.P2 D05.P2
-IM6: A05.S2 D05.S2
-IM7: A05.T2 D05.T2
-IM8: A05.V2 D05.V2
-IM9: A06.D2 D06.D2
-IM10: A06.E2 D06.E2
-IM11: A06.H2 D06.H2
-INTERRUPT: A06.M2 D06.M2
-SKIP: A06.K2 D06.K2
BRK_SYNC_CLK: A06.T2 D06.T2 ; also sheet 1
BT1B: A02.S2 D02.S2 ; also sheet 1
IOP1: A02.K2 D02.K2
IOP2: A02.M2 D02.M2
IOP4: A02.P2 D02.P2
POWER_CLEAR: A02.V2 D02.V2 ; also sheet 1
RUN: A06.S2 D06.S2
T2: A02.T2 D02.T2 ; also sheet 1
Unconnected: A06.V2 D06.V2

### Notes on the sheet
- Unused Slots:
- I/O Connectors
- D-BS-DM01-0-6 | B

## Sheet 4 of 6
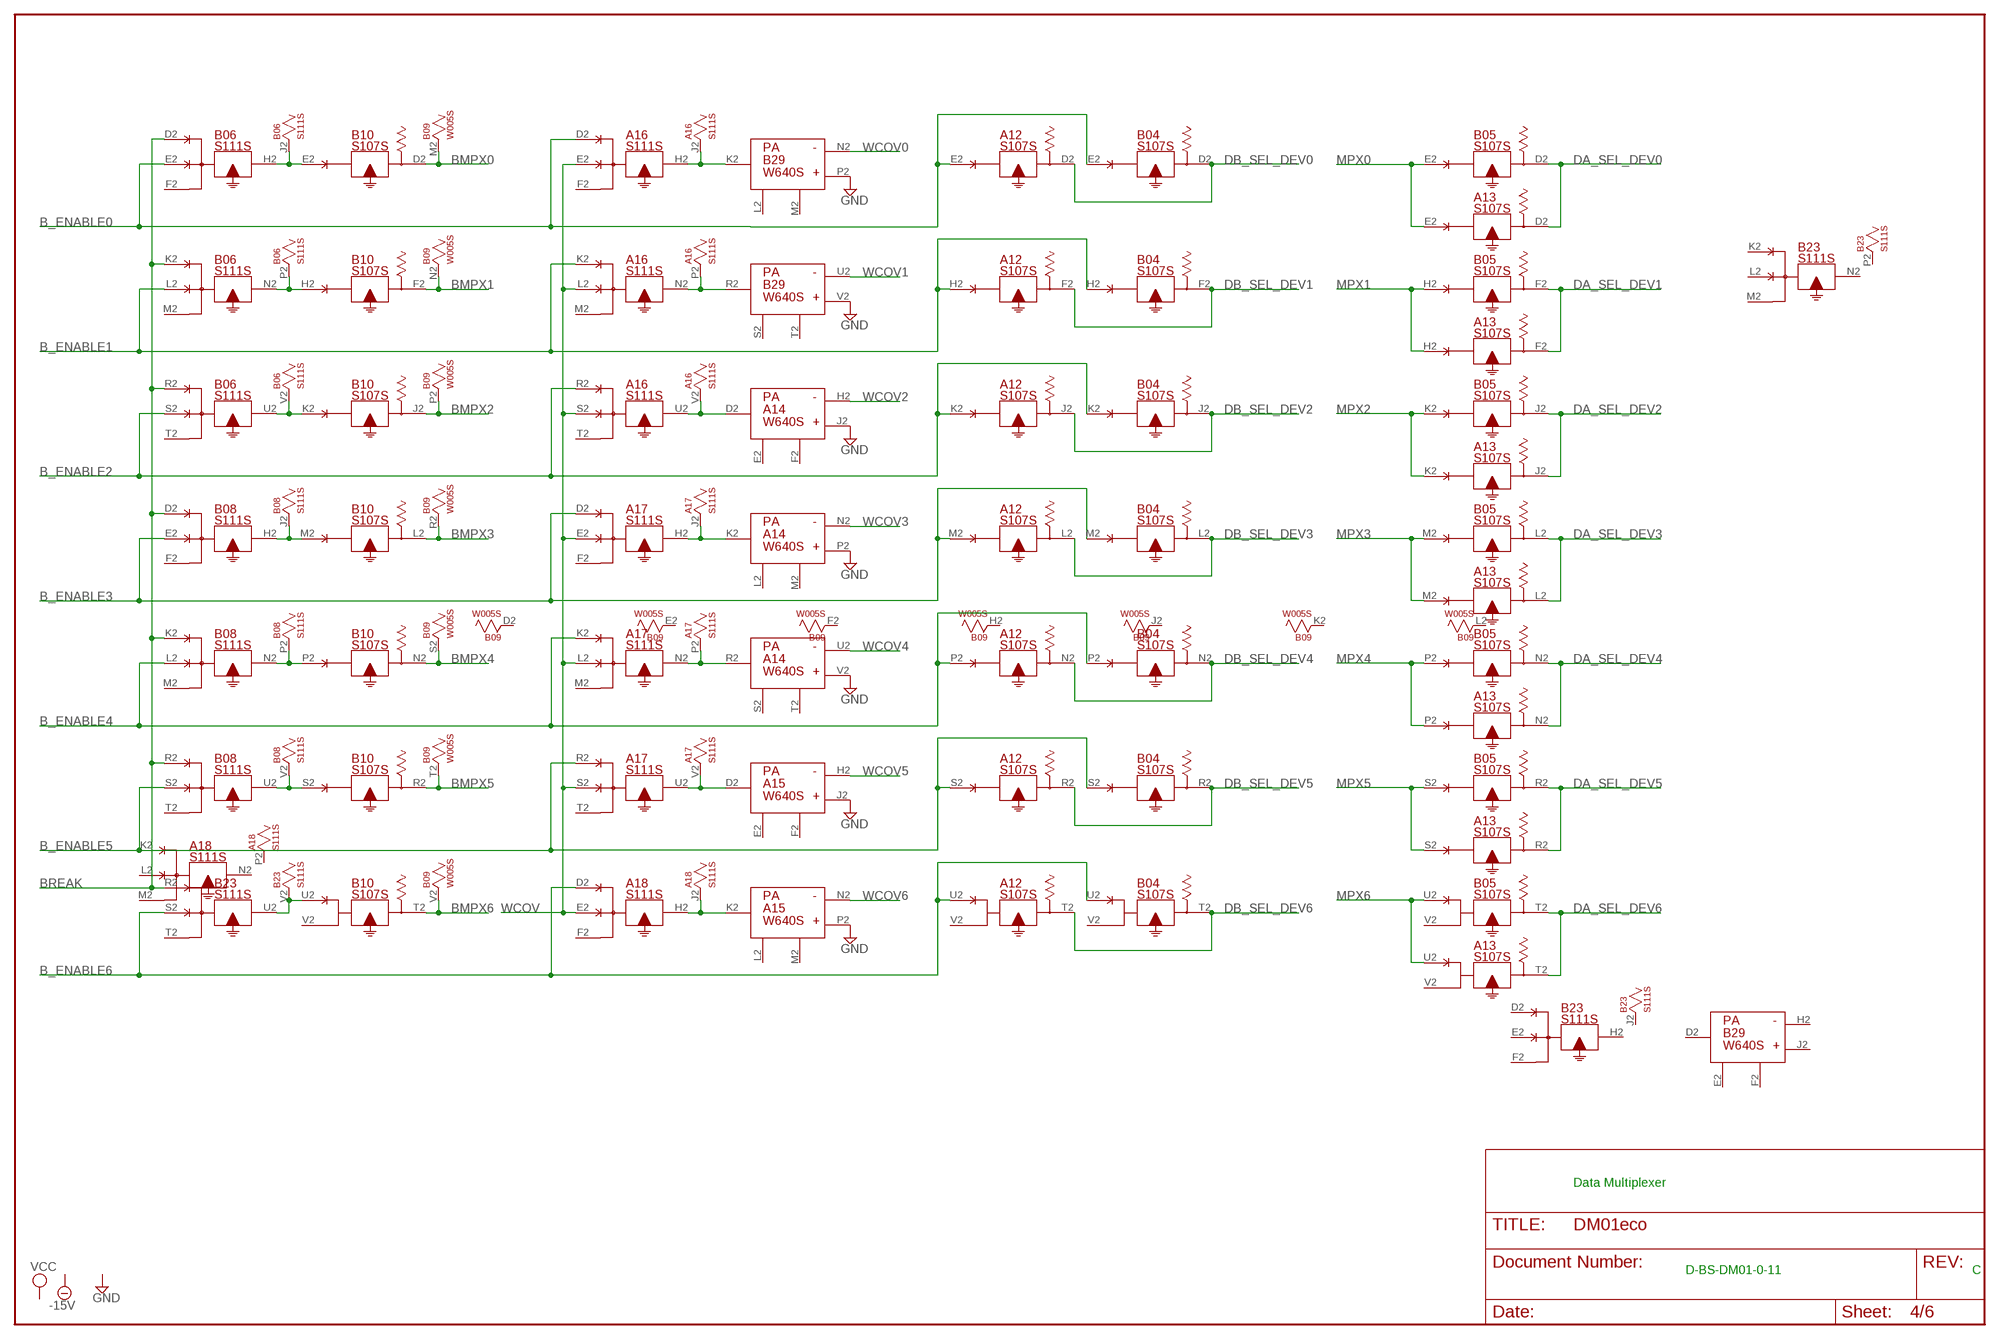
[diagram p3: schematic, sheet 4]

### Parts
A12  S107S  R107S  [H807S]
A13  S107S  R107S  [H807S]
A14  W640S  [H807S]
A15  W640S  [H807S]
A16  S111S  R111S  [H807S]
A17  S111S  R111S  [H807S]
B04  S107S  R107S  [H807S]
B05  S107S  R107S  [H807S]
B06  S111S  R111S  [H807S]
B08  S111S  R111S  [H807S]
B10  S107S  R107S  [H807S]

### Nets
B_ENABLE0: A12.E2(D:I$1) A16.D2(H:I$1) B04.E2(D:I$1) B06.E2(H:I$2) ; also sheet 1,2
B_ENABLE1: A12.H2(F:I$1) A16.K2(N:I$1) B04.H2(F:I$1) B06.L2(N:I$2) ; also sheet 1,2
B_ENABLE2: A12.K2(J:I$1) A16.R2(U:I$1) B04.K2(J:I$1) B06.S2(U:I$2) ; also sheet 1,2
B_ENABLE3: A12.M2(L:I$1) A17.D2(H:I$1) B04.M2(L:I$1) B08.E2(H:I$2) ; also sheet 1,2
B_ENABLE4: A12.P2(N:I$1) A17.K2(N:I$1) B04.P2(N:I$1) B08.L2(N:I$2) ; also sheet 1,2
B_ENABLE5: A12.S2(R:I$1) A17.R2(U:I$1) B04.S2(R:I$1) B08.S2(U:I$2) ; also sheet 1,2
B_ENABLE6: A12.U2(T:I$1) A18.D2(H:I$1) B04.U2(T:I$1) B23.S2(U:I$2) ; also sheet 1,2
BMPX0: B09.M2 B10.D2(D:O$1) ; also sheet 2
BMPX1: B09.N2 B10.F2(F:O$1) ; also sheet 2
BMPX2: B09.P2 B10.J2(J:O$1) ; also sheet 2
BMPX3: B09.R2 B10.L2(L:O$1) ; also sheet 2
BMPX4: B09.S2 B10.N2(N:O$1) ; also sheet 2
BMPX5: B09.T2 B10.R2(R:O$1) ; also sheet 2
BMPX6: B09.V2 B10.T2(T:O$1) ; also sheet 2
BREAK: B06.D2(H:I$1) B06.K2(N:I$1) B06.R2(U:I$1) B08.D2(H:I$1) B08.K2(N:I$1) B08.R2(U:I$1) B23.R2(U:I$1) ; also sheet 1,2
DA_SEL_DEV0: A13.D2(D:O$1) B05.D2(D:O$1) ; also sheet 5
DA_SEL_DEV1: A13.F2(F:O$1) B05.F2(F:O$1) ; also sheet 5
DA_SEL_DEV2: A13.J2(J:O$1) B05.J2(J:O$1) ; also sheet 5
DA_SEL_DEV3: A13.L2(L:O$1) B05.L2(L:O$1) ; also sheet 5
DA_SEL_DEV4: A13.N2(N:O$1) B05.N2(N:O$1) ; also sheet 5
DA_SEL_DEV5: A13.R2(R:O$1) B05.R2(R:O$1) ; also sheet 5
DA_SEL_DEV6: A13.T2(T:O$1) B05.T2(T:O$1) ; also sheet 5
DB_SEL_DEV0: A12.D2(D:O$1) B04.D2(D:O$1) ; also sheet 6
DB_SEL_DEV1: A12.F2(F:O$1) B04.F2(F:O$1) ; also sheet 6
DB_SEL_DEV2: A12.J2(J:O$1) B04.J2(J:O$1) ; also sheet 6
DB_SEL_DEV3: A12.L2(L:O$1) B04.L2(L:O$1) ; also sheet 6
DB_SEL_DEV4: A12.N2(N:O$1) B04.N2(N:O$1) ; also sheet 6
DB_SEL_DEV5: A12.R2(R:O$1) B04.R2(R:O$1) ; also sheet 6
DB_SEL_DEV6: A12.T2(T:O$1) B04.T2(T:O$1) ; also sheet 6
GND [Supply]: A14.J2(J) A14.P2(J) A14.V2(J) A15.J2(J) A15.P2(J) B29.P2(J) B29.V2(J) ; also sheet 1
MPX0: A13.E2(D:I$1) B05.E2(D:I$1) ; also sheet 1,2
MPX1: A13.H2(F:I$1) B05.H2(F:I$1) ; also sheet 1,2
MPX2: A13.K2(J:I$1) B05.K2(J:I$1) ; also sheet 1,2
MPX3: A13.M2(L:I$1) B05.M2(L:I$1) ; also sheet 1,2
MPX4: A13.P2(N:I$1) B05.P2(N:I$1) ; also sheet 1,2
MPX5: A13.S2(R:I$1) B05.S2(R:I$1) ; also sheet 1,2
MPX6: A13.U2(T:I$1) B05.U2(T:I$1) ; also sheet 1,2
N$49: A16.H2(H:O$1) A16.J2 B29.K2(D)
N$50: A16.N2(N:O$1) A16.P2 B29.R2(D)
N$51: A14.D2(D) A16.U2(U:O$1) A16.V2
N$52: A14.K2(D) A17.H2(H:O$1) A17.J2
N$53: A14.R2(D) A17.N2(N:O$1) A17.P2
N$54: A15.D2(D) A17.U2(U:O$1) A17.V2
N$55: A15.K2(D) A18.H2(H:O$1) A18.J2
N$64: B06.H2(H:O$1) B06.J2 B10.E2(D:I$1)
N$65: B06.N2(N:O$1) B06.P2 B10.H2(F:I$1)
N$66: B10.U2(T:I$1) B23.U2(U:O$1) B23.V2
N$67: B08.U2(U:O$1) B08.V2 B10.S2(R:I$1)
N$68: B08.N2(N:O$1) B08.P2 B10.P2(N:I$1)
N$69: B08.H2(H:O$1) B08.J2 B10.M2(L:I$1)
N$70: B06.U2(U:O$1) B06.V2 B10.K2(J:I$1)
WCOV: A16.E2(H:I$2) A16.L2(N:I$2) A16.S2(U:I$2) A17.E2(H:I$2) A17.L2(N:I$2) A17.S2(U:I$2) A18.E2(H:I$2) ; also sheet 2
WCOV0: B29.N2(H) ; also sheet 2
WCOV1: B29.U2(H) ; also sheet 2
WCOV2: A14.H2(H) ; also sheet 2
WCOV3: A14.N2(H) ; also sheet 2
WCOV4: A14.U2(H) ; also sheet 2
WCOV5: A15.H2(H) ; also sheet 2
WCOV6: A15.N2(H) ; also sheet 2
Unconnected: A12.V2(T:I$2) A13.V2(T:I$2) A14.E2(E) A14.F2(F) A14.L2(E) A14.M2(F) A14.S2(E) A14.T2(F) A15.E2(E) A15.F2(F) A15.L2(E) A15.M2(F) A15.R2(D) A15.S2(E) A15.T2(F) A15.U2(H) A15.V2(J) A16.F2(H:I$3) A16.M2(N:I$3) A16.T2(U:I$3) A17.F2(H:I$3) A17.M2(N:I$3) A17.T2(U:I$3) A18.F2(H:I$3) A18.L2(N:I$2) A18.M2(N:I$3) B04.V2(T:I$2) B05.V2(T:I$2) B06.F2(H:I$3) B06.M2(N:I$3) B06.T2(U:I$3) B08.F2(H:I$3) B08.M2(N:I$3) B08.T2(U:I$3) B10.V2(T:I$2) B23.F2(H:I$3) B23.T2(U:I$3) B29.E2(E) B29.F2(F) B29.L2(E) B29.M2(F) B29.S2(E) B29.T2(F)

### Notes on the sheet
- Data Multiplexer
- D-BS-DM01-0-11 | C

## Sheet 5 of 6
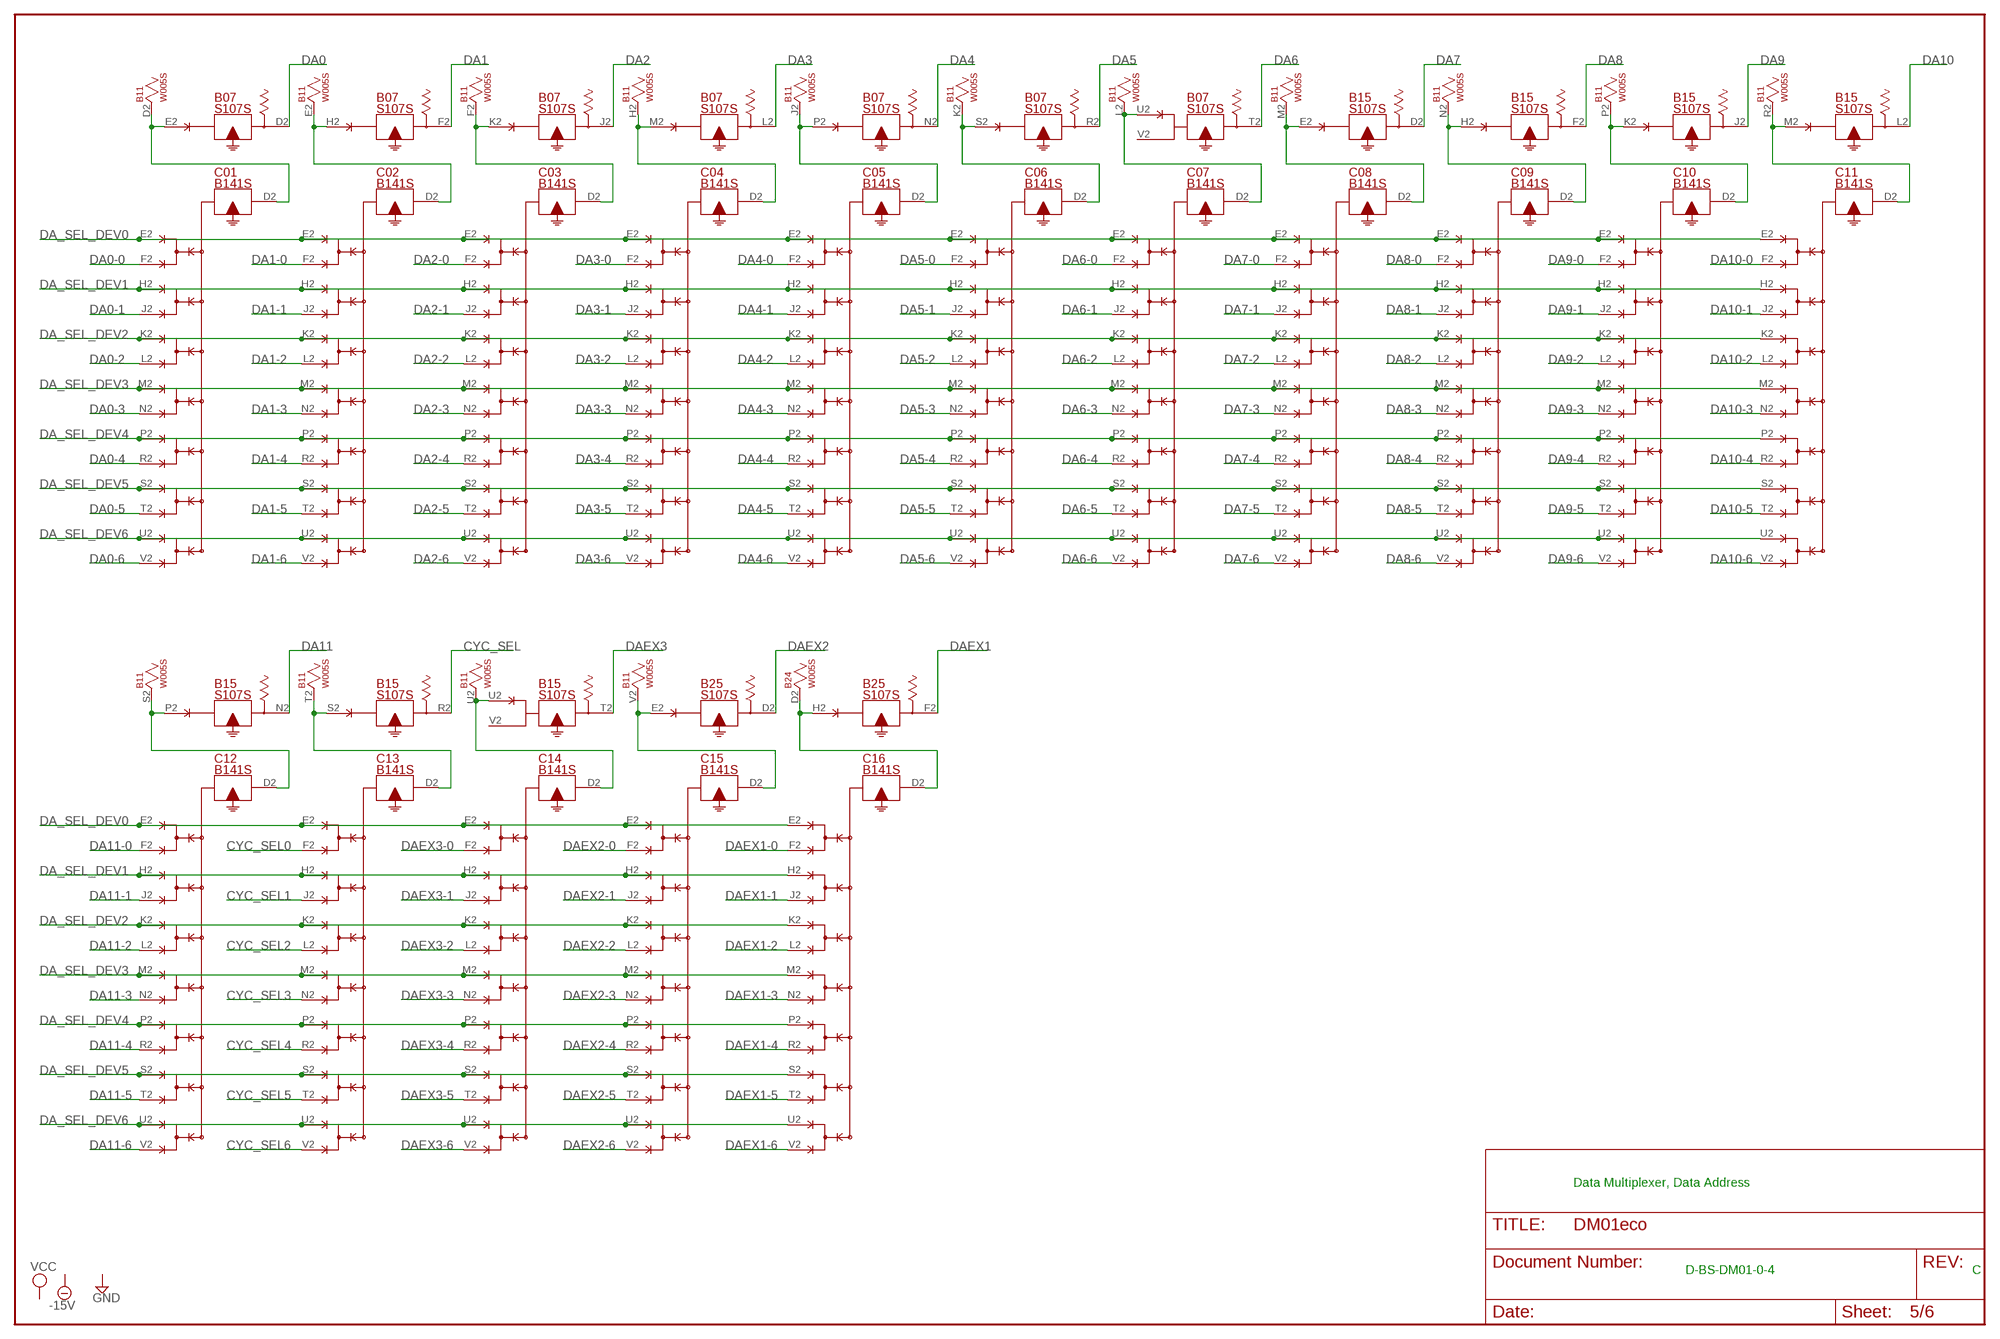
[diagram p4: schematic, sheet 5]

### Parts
B07  S107S  R107S  [H807S]
B11  W005S  [H807S]
B15  S107S  R107S  [H807S]
B24  W005S  [H807S]
B25  S107S  R107S  [H807S]
C01  B141S  R141S  [H807S]
C02  B141S  R141S  [H807S]
C03  B141S  R141S  [H807S]
C04  B141S  R141S  [H807S]
C05  B141S  R141S  [H807S]
C06  B141S  R141S  [H807S]
C07  B141S  R141S  [H807S]
C08  B141S  R141S  [H807S]
C09  B141S  R141S  [H807S]
C10  B141S  R141S  [H807S]
C11  B141S  R141S  [H807S]
C12  B141S  R141S  [H807S]
C13  B141S  R141S  [H807S]
C14  B141S  R141S  [H807S]
C15  B141S  R141S  [H807S]
C16  B141S  R141S  [H807S]

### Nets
CYC_SEL: B15.R2(R:O$1) ; also sheet 1,2
CYC_SEL0: C13.F2(F) ; also sheet 2
CYC_SEL1: C13.J2(J) ; also sheet 2
CYC_SEL2: C13.L2(L) ; also sheet 2
CYC_SEL3: C13.N2(N) ; also sheet 2
CYC_SEL4: C13.R2(R) ; also sheet 2
CYC_SEL5: C13.T2(T) ; also sheet 2
CYC_SEL6: C13.V2(V) ; also sheet 2
DA0: B07.D2(D:O$1) ; also sheet 2
DA0-0: C01.F2(F) ; also sheet 2
DA0-1: C01.J2(J) ; also sheet 2
DA0-2: C01.L2(L) ; also sheet 2
DA0-3: C01.N2(N) ; also sheet 2
DA0-4: C01.R2(R) ; also sheet 2
DA0-5: C01.T2(T) ; also sheet 2
DA0-6: C01.V2(V) ; also sheet 2
DA1: B07.F2(F:O$1) ; also sheet 2
DA1-0: C02.F2(F) ; also sheet 2
DA1-1: C02.J2(J) ; also sheet 2
DA1-2: C02.L2(L) ; also sheet 2
DA1-3: C02.N2(N) ; also sheet 2
DA1-4: C02.R2(R) ; also sheet 2
DA1-5: C02.T2(T) ; also sheet 2
DA1-6: C02.V2(V) ; also sheet 2
DA2: B07.J2(J:O$1) ; also sheet 2
DA2-0: C03.F2(F) ; also sheet 2
DA2-1: C03.J2(J) ; also sheet 2
DA2-2: C03.L2(L) ; also sheet 2
DA2-3: C03.N2(N) ; also sheet 2
DA2-4: C03.R2(R) ; also sheet 2
DA2-5: C03.T2(T) ; also sheet 2
DA2-6: C03.V2(V) ; also sheet 2
DA3: B07.L2(L:O$1) ; also sheet 2
DA3-0: C04.F2(F) ; also sheet 2
DA3-1: C04.J2(J) ; also sheet 2
DA3-2: C04.L2(L) ; also sheet 2
DA3-3: C04.N2(N) ; also sheet 2
DA3-4: C04.R2(R) ; also sheet 2
DA3-5: C04.T2(T) ; also sheet 2
DA3-6: C04.V2(V) ; also sheet 2
DA4: B07.N2(N:O$1) ; also sheet 2
DA4-0: C05.F2(F) ; also sheet 2
DA4-1: C05.J2(J) ; also sheet 2
DA4-2: C05.L2(L) ; also sheet 2
DA4-3: C05.N2(N) ; also sheet 2
DA4-4: C05.R2(R) ; also sheet 2
DA4-5: C05.T2(T) ; also sheet 2
DA4-6: C05.V2(V) ; also sheet 2
DA5: B07.R2(R:O$1) ; also sheet 2
DA5-0: C06.F2(F) ; also sheet 2
DA5-1: C06.J2(J) ; also sheet 2
DA5-2: C06.L2(L) ; also sheet 2
DA5-3: C06.N2(N) ; also sheet 2
DA5-4: C06.R2(R) ; also sheet 2
DA5-5: C06.T2(T) ; also sheet 2
DA5-6: C06.V2(V) ; also sheet 2
DA6: B07.T2(T:O$1) ; also sheet 2
DA6-0: C07.F2(F) ; also sheet 2
DA6-1: C07.J2(J) ; also sheet 2
DA6-2: C07.L2(L) ; also sheet 2
DA6-3: C07.N2(N) ; also sheet 2
DA6-4: C07.R2(R) ; also sheet 2
DA6-5: C07.T2(T) ; also sheet 2
DA6-6: C07.V2(V) ; also sheet 2
DA7: B15.D2(D:O$1) ; also sheet 2
DA7-0: C08.F2(F) ; also sheet 2
DA7-1: C08.J2(J) ; also sheet 2
DA7-2: C08.L2(L) ; also sheet 2
DA7-3: C08.N2(N) ; also sheet 2
DA7-4: C08.R2(R) ; also sheet 2
DA7-5: C08.T2(T) ; also sheet 2
DA7-6: C08.V2(V) ; also sheet 2
DA8: B15.F2(F:O$1) ; also sheet 2
DA8-0: C09.F2(F) ; also sheet 2
DA8-1: C09.J2(J) ; also sheet 2
DA8-2: C09.L2(L) ; also sheet 2
DA8-3: C09.N2(N) ; also sheet 2
DA8-4: C09.R2(R) ; also sheet 2
DA8-5: C09.T2(T) ; also sheet 2
DA8-6: C09.V2(V) ; also sheet 2
DA9: B15.J2(J:O$1) ; also sheet 2
DA9-0: C10.F2(F) ; also sheet 2
DA9-1: C10.J2(J) ; also sheet 2
DA9-2: C10.L2(L) ; also sheet 2
DA9-3: C10.N2(N) ; also sheet 2
DA9-4: C10.R2(R) ; also sheet 2
DA9-5: C10.T2(T) ; also sheet 2
DA9-6: C10.V2(V) ; also sheet 2
DA10: B15.L2(L:O$1) ; also sheet 2
DA10-0: C11.F2(F) ; also sheet 2
DA10-1: C11.J2(J) ; also sheet 2
DA10-2: C11.L2(L) ; also sheet 2
DA10-3: C11.N2(N) ; also sheet 2
DA10-4: C11.R2(R) ; also sheet 2
DA10-5: C11.T2(T) ; also sheet 2
DA10-6: C11.V2(V) ; also sheet 2
DA11: B15.N2(N:O$1) ; also sheet 2
DA11-0: C12.F2(F) ; also sheet 2
DA11-1: C12.J2(J) ; also sheet 2
DA11-2: C12.L2(L) ; also sheet 2
DA11-3: C12.N2(N) ; also sheet 2
DA11-4: C12.R2(R) ; also sheet 2
DA11-5: C12.T2(T) ; also sheet 2
DA11-6: C12.V2(V) ; also sheet 2
DA_SEL_DEV0: C01.E2(E) C02.E2(E) C03.E2(E) C04.E2(E) C05.E2(E) C06.E2(E) C07.E2(E) C08.E2(E) C09.E2(E) C10.E2(E) C11.E2(E) C12.E2(E) C13.E2(E) C14.E2(E) C15.E2(E) C16.E2(E) ; also sheet 4
DA_SEL_DEV1: C01.H2(H) C02.H2(H) C03.H2(H) C04.H2(H) C05.H2(H) C06.H2(H) C07.H2(H) C08.H2(H) C09.H2(H) C10.H2(H) C11.H2(H) C12.H2(H) C13.H2(H) C14.H2(H) C15.H2(H) C16.H2(H) ; also sheet 4
DA_SEL_DEV2: C01.K2(K) C02.K2(K) C03.K2(K) C04.K2(K) C05.K2(K) C06.K2(K) C07.K2(K) C08.K2(K) C09.K2(K) C10.K2(K) C11.K2(K) C12.K2(K) C13.K2(K) C14.K2(K) C15.K2(K) C16.K2(K) ; also sheet 4
DA_SEL_DEV3: C01.M2(M) C02.M2(M) C03.M2(M) C04.M2(M) C05.M2(M) C06.M2(M) C07.M2(M) C08.M2(M) C09.M2(M) C10.M2(M) C11.M2(M) C12.M2(M) C13.M2(M) C14.M2(M) C15.M2(M) C16.M2(M) ; also sheet 4
DA_SEL_DEV4: C01.P2(P) C02.P2(P) C03.P2(P) C04.P2(P) C05.P2(P) C06.P2(P) C07.P2(P) C08.P2(P) C09.P2(P) C10.P2(P) C11.P2(P) C12.P2(P) C13.P2(P) C14.P2(P) C15.P2(P) C16.P2(P) ; also sheet 4
DA_SEL_DEV5: C01.S2(S) C02.S2(S) C03.S2(S) C04.S2(S) C05.S2(S) C06.S2(S) C07.S2(S) C08.S2(S) C09.S2(S) C10.S2(S) C11.S2(S) C12.S2(S) C13.S2(S) C14.S2(S) C15.S2(S) C16.S2(S) ; also sheet 4
DA_SEL_DEV6: C01.U2(U) C02.U2(U) C03.U2(U) C04.U2(U) C05.U2(U) C06.U2(U) C07.U2(U) C08.U2(U) C09.U2(U) C10.U2(U) C11.U2(U) C12.U2(U) C13.U2(U) C14.U2(U) C15.U2(U) C16.U2(U) ; also sheet 4
DAEX1: B25.F2(F:O$1) ; also sheet 2
DAEX1-0: C16.F2(F) ; also sheet 2
DAEX1-1: C16.J2(J) ; also sheet 2
DAEX1-2: C16.L2(L) ; also sheet 2
DAEX1-3: C16.N2(N) ; also sheet 2
DAEX1-4: C16.R2(R) ; also sheet 2
DAEX1-5: C16.T2(T) ; also sheet 2
DAEX1-6: C16.V2(V) ; also sheet 2
DAEX2: B25.D2(D:O$1) ; also sheet 2
DAEX2-0: C15.F2(F) ; also sheet 2
DAEX2-1: C15.J2(J) ; also sheet 2
DAEX2-2: C15.L2(L) ; also sheet 2
DAEX2-3: C15.N2(N) ; also sheet 2
DAEX2-4: C15.R2(R) ; also sheet 2
DAEX2-5: C15.T2(T) ; also sheet 2
DAEX2-6: C15.V2(V) ; also sheet 2
DAEX3: B15.T2(T:O$1) ; also sheet 2
DAEX3-0: C14.F2(F) ; also sheet 2
DAEX3-1: C14.J2(J) ; also sheet 2
DAEX3-2: C14.L2(L) ; also sheet 2
DAEX3-3: C14.N2(N) ; also sheet 2
DAEX3-4: C14.R2(R) ; also sheet 2
DAEX3-5: C14.T2(T) ; also sheet 2
DAEX3-6: C14.V2(V) ; also sheet 2
N$56: B07.E2(D:I$1) B11.D2 C01.D2(D)
N$57: B07.U2(T:I$1) B11.L2 C07.D2(D)
N$58: B07.H2(F:I$1) B11.E2 C02.D2(D)
N$59: B07.K2(J:I$1) B11.F2 C03.D2(D)
N$60: B07.M2(L:I$1) B11.H2 C04.D2(D)
N$61: B07.P2(N:I$1) B11.J2 C05.D2(D)
N$62: B07.S2(R:I$1) B11.K2 C06.D2(D)
N$63: B11.M2 B15.E2(D:I$1) C08.D2(D)
N$71: B11.N2 B15.H2(F:I$1) C09.D2(D)
N$72: B11.P2 B15.K2(J:I$1) C10.D2(D)
N$73: B11.R2 B15.M2(L:I$1) C11.D2(D)
N$74: B11.S2 B15.P2(N:I$1) C12.D2(D)
N$75: B11.T2 B15.S2(R:I$1) C13.D2(D)
N$76: B11.U2 B15.U2(T:I$1) C14.D2(D)
N$77: B11.V2 B25.E2(D:I$1) C15.D2(D)
N$78: B24.D2 B25.H2(F:I$1) C16.D2(D)
Unconnected: B07.V2(T:I$2) B15.V2(T:I$2)

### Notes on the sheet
- Data Multiplexer, Data Address
- D-BS-DM01-0-4 | C

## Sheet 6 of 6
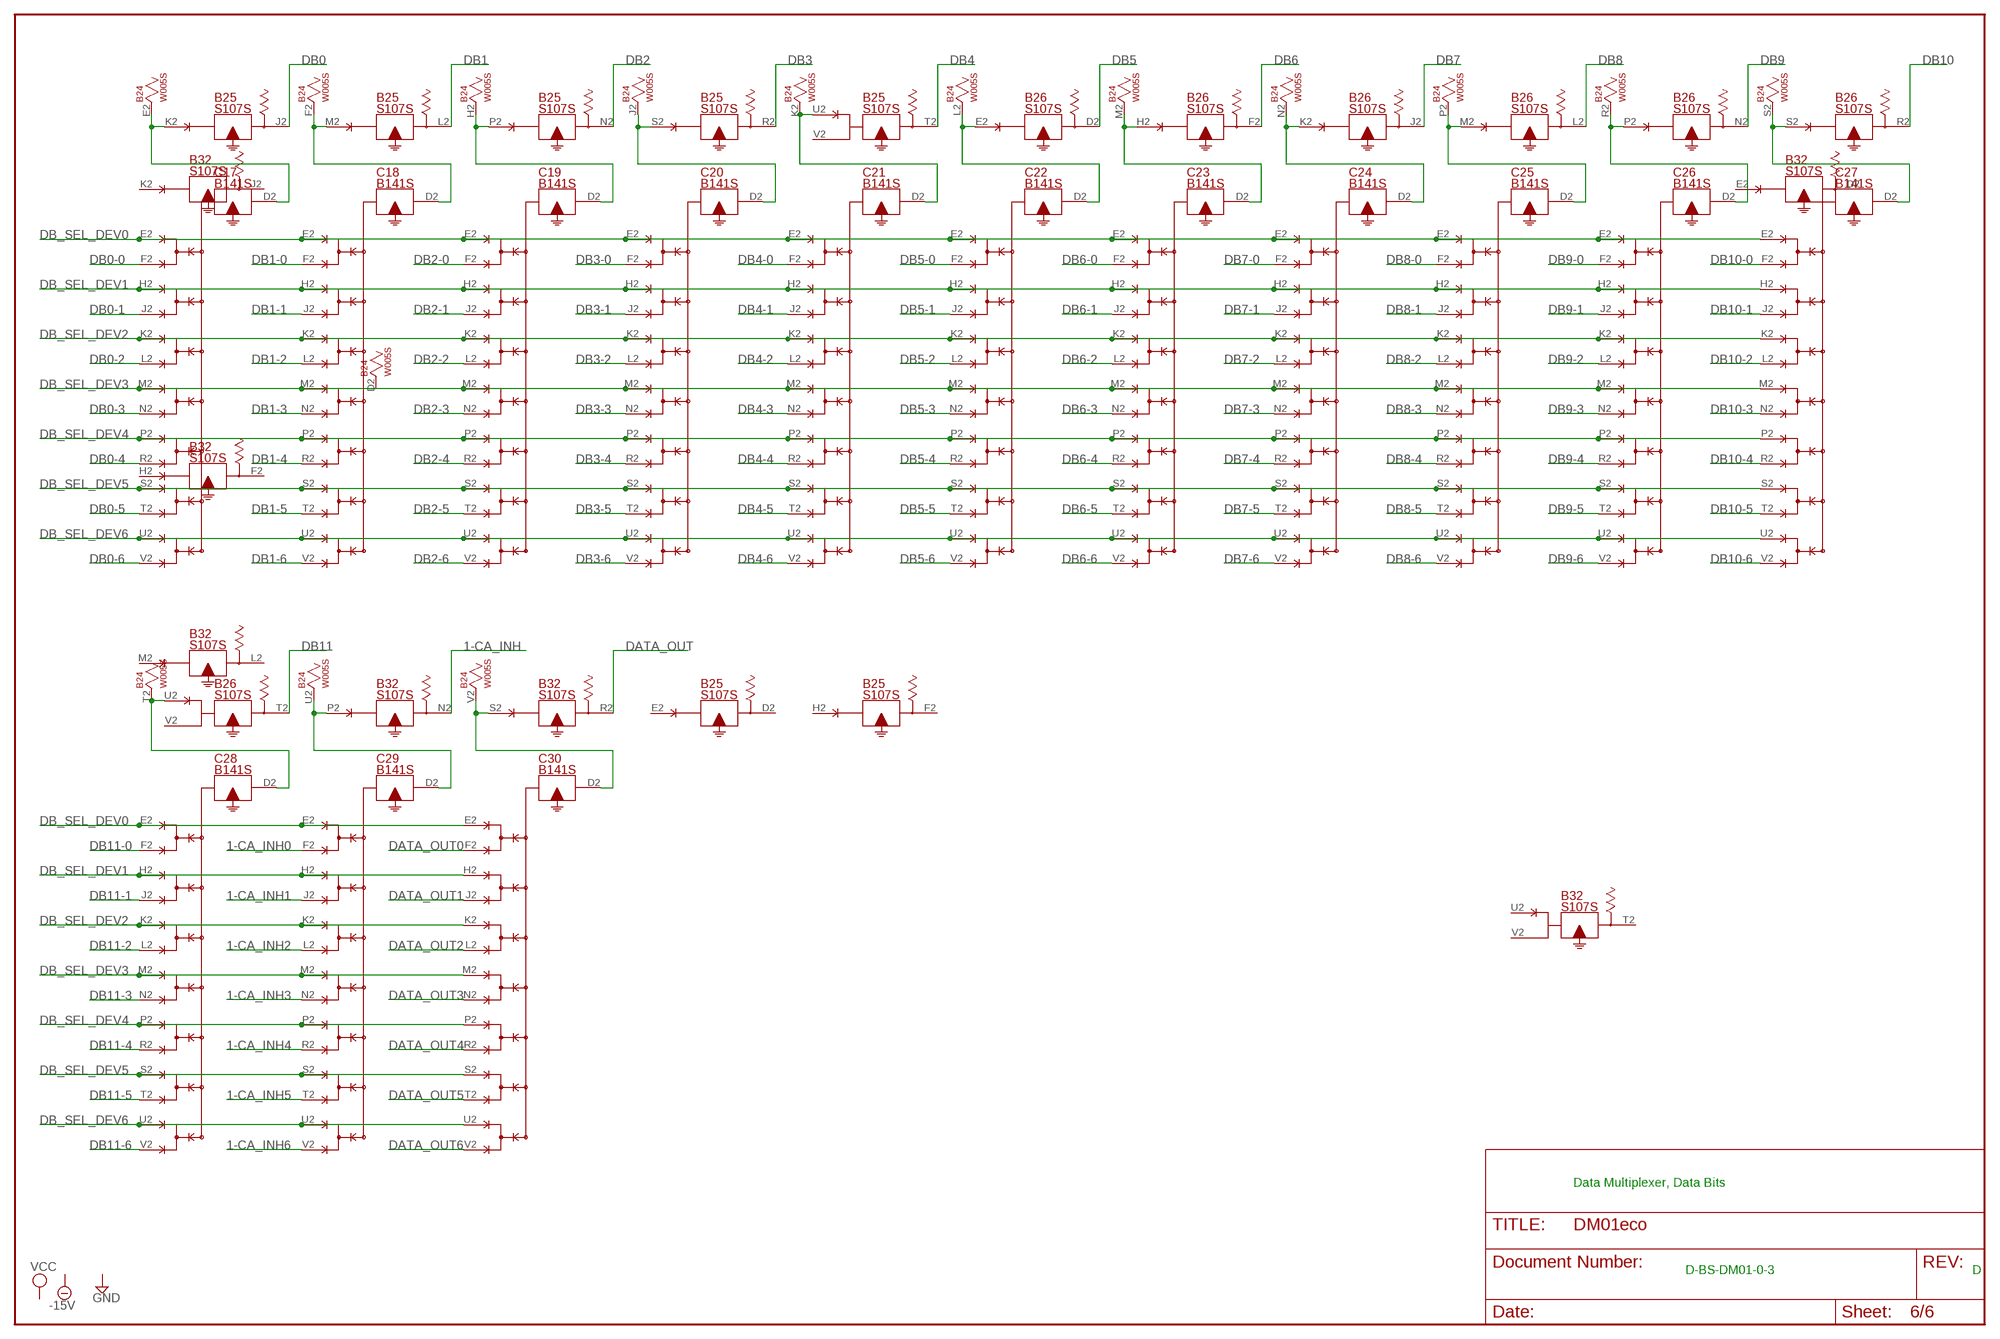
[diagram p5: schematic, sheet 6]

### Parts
B26  S107S  R107S  [H807S]
C17  B141S  R141S  [H807S]
C18  B141S  R141S  [H807S]
C19  B141S  R141S  [H807S]
C20  B141S  R141S  [H807S]
C21  B141S  R141S  [H807S]
C22  B141S  R141S  [H807S]
C23  B141S  R141S  [H807S]
C24  B141S  R141S  [H807S]
C25  B141S  R141S  [H807S]
C26  B141S  R141S  [H807S]
C27  B141S  R141S  [H807S]
C28  B141S  R141S  [H807S]
C29  B141S  R141S  [H807S]
C30  B141S  R141S  [H807S]

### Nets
1-CA_INH: B32.N2(N:O$1) ; also sheet 2
1-CA_INH0: C29.F2(F) ; also sheet 2
1-CA_INH1: C29.J2(J) ; also sheet 2
1-CA_INH2: C29.L2(L) ; also sheet 2
1-CA_INH3: C29.N2(N) ; also sheet 2
1-CA_INH4: C29.R2(R) ; also sheet 2
1-CA_INH5: C29.T2(T) ; also sheet 2
1-CA_INH6: C29.V2(V) ; also sheet 2
DATA_OUT: B32.R2(R:O$1) ; also sheet 2
DATA_OUT0: C30.F2(F) ; also sheet 2
DATA_OUT1: C30.J2(J) ; also sheet 2
DATA_OUT2: C30.L2(L) ; also sheet 2
DATA_OUT3: C30.N2(N) ; also sheet 2
DATA_OUT4: C30.R2(R) ; also sheet 2
DATA_OUT5: C30.T2(T) ; also sheet 2
DATA_OUT6: C30.V2(V) ; also sheet 2
DB0: B25.J2(J:O$1) ; also sheet 2
DB0-0: C17.F2(F) ; also sheet 2
DB0-1: C17.J2(J) ; also sheet 2
DB0-2: C17.L2(L) ; also sheet 2
DB0-3: C17.N2(N) ; also sheet 2
DB0-4: C17.R2(R) ; also sheet 2
DB0-5: C17.T2(T) ; also sheet 2
DB0-6: C17.V2(V) ; also sheet 2
DB1: B25.L2(L:O$1) ; also sheet 2
DB1-0: C18.F2(F) ; also sheet 2
DB1-1: C18.J2(J) ; also sheet 2
DB1-2: C18.L2(L) ; also sheet 2
DB1-3: C18.N2(N) ; also sheet 2
DB1-4: C18.R2(R) ; also sheet 2
DB1-5: C18.T2(T) ; also sheet 2
DB1-6: C18.V2(V) ; also sheet 2
DB2: B25.N2(N:O$1) ; also sheet 2
DB2-0: C19.F2(F) ; also sheet 2
DB2-1: C19.J2(J) ; also sheet 2
DB2-2: C19.L2(L) ; also sheet 2
DB2-3: C19.N2(N) ; also sheet 2
DB2-4: C19.R2(R) ; also sheet 2
DB2-5: C19.T2(T) ; also sheet 2
DB2-6: C19.V2(V) ; also sheet 2
DB3: B25.R2(R:O$1) ; also sheet 2
DB3-0: C20.F2(F) ; also sheet 2
DB3-1: C20.J2(J) ; also sheet 2
DB3-2: C20.L2(L) ; also sheet 2
DB3-3: C20.N2(N) ; also sheet 2
DB3-4: C20.R2(R) ; also sheet 2
DB3-5: C20.T2(T) ; also sheet 2
DB3-6: C20.V2(V) ; also sheet 2
DB4: B25.T2(T:O$1) ; also sheet 2
DB4-0: C21.F2(F) ; also sheet 2
DB4-1: C21.J2(J) ; also sheet 2
DB4-2: C21.L2(L) ; also sheet 2
DB4-3: C21.N2(N) ; also sheet 2
DB4-4: C21.R2(R) ; also sheet 2
DB4-5: C21.T2(T) ; also sheet 2
DB4-6: C21.V2(V) ; also sheet 2
DB5: B26.D2(D:O$1) ; also sheet 2
DB5-0: C22.F2(F) ; also sheet 2
DB5-1: C22.J2(J) ; also sheet 2
DB5-2: C22.L2(L) ; also sheet 2
DB5-3: C22.N2(N) ; also sheet 2
DB5-4: C22.R2(R) ; also sheet 2
DB5-5: C22.T2(T) ; also sheet 2
DB5-6: C22.V2(V) ; also sheet 2
DB6: B26.F2(F:O$1) ; also sheet 2
DB6-0: C23.F2(F) ; also sheet 2
DB6-1: C23.J2(J) ; also sheet 2
DB6-2: C23.L2(L) ; also sheet 2
DB6-3: C23.N2(N) ; also sheet 2
DB6-4: C23.R2(R) ; also sheet 2
DB6-5: C23.T2(T) ; also sheet 2
DB6-6: C23.V2(V) ; also sheet 2
DB7: B26.J2(J:O$1) ; also sheet 2
DB7-0: C24.F2(F) ; also sheet 2
DB7-1: C24.J2(J) ; also sheet 2
DB7-2: C24.L2(L) ; also sheet 2
DB7-3: C24.N2(N) ; also sheet 2
DB7-4: C24.R2(R) ; also sheet 2
DB7-5: C24.T2(T) ; also sheet 2
DB7-6: C24.V2(V) ; also sheet 2
DB8: B26.L2(L:O$1) ; also sheet 2
DB8-0: C25.F2(F) ; also sheet 2
DB8-1: C25.J2(J) ; also sheet 2
DB8-2: C25.L2(L) ; also sheet 2
DB8-3: C25.N2(N) ; also sheet 2
DB8-4: C25.R2(R) ; also sheet 2
DB8-5: C25.T2(T) ; also sheet 2
DB8-6: C25.V2(V) ; also sheet 2
DB9: B26.N2(N:O$1) ; also sheet 2
DB9-0: C26.F2(F) ; also sheet 2
DB9-1: C26.J2(J) ; also sheet 2
DB9-2: C26.L2(L) ; also sheet 2
DB9-3: C26.N2(N) ; also sheet 2
DB9-4: C26.R2(R) ; also sheet 2
DB9-5: C26.T2(T) ; also sheet 2
DB9-6: C26.V2(V) ; also sheet 2
DB10: B26.R2(R:O$1) ; also sheet 2
DB10-0: C27.F2(F) ; also sheet 2
DB10-1: C27.J2(J) ; also sheet 2
DB10-2: C27.L2(L) ; also sheet 2
DB10-3: C27.N2(N) ; also sheet 2
DB10-4: C27.R2(R) ; also sheet 2
DB10-5: C27.T2(T) ; also sheet 2
DB10-6: C27.V2(V) ; also sheet 2
DB11: B26.T2(T:O$1) ; also sheet 2
DB11-0: C28.F2(F) ; also sheet 2
DB11-1: C28.J2(J) ; also sheet 2
DB11-2: C28.L2(L) ; also sheet 2
DB11-3: C28.N2(N) ; also sheet 2
DB11-4: C28.R2(R) ; also sheet 2
DB11-5: C28.T2(T) ; also sheet 2
DB11-6: C28.V2(V) ; also sheet 2
DB_SEL_DEV0: C17.E2(E) C18.E2(E) C19.E2(E) C20.E2(E) C21.E2(E) C22.E2(E) C23.E2(E) C24.E2(E) C25.E2(E) C26.E2(E) C27.E2(E) C28.E2(E) C29.E2(E) C30.E2(E) ; also sheet 4
DB_SEL_DEV1: C17.H2(H) C18.H2(H) C19.H2(H) C20.H2(H) C21.H2(H) C22.H2(H) C23.H2(H) C24.H2(H) C25.H2(H) C26.H2(H) C27.H2(H) C28.H2(H) C29.H2(H) C30.H2(H) ; also sheet 4
DB_SEL_DEV2: C17.K2(K) C18.K2(K) C19.K2(K) C20.K2(K) C21.K2(K) C22.K2(K) C23.K2(K) C24.K2(K) C25.K2(K) C26.K2(K) C27.K2(K) C28.K2(K) C29.K2(K) C30.K2(K) ; also sheet 4
DB_SEL_DEV3: C17.M2(M) C18.M2(M) C19.M2(M) C20.M2(M) C21.M2(M) C22.M2(M) C23.M2(M) C24.M2(M) C25.M2(M) C26.M2(M) C27.M2(M) C28.M2(M) C29.M2(M) C30.M2(M) ; also sheet 4
DB_SEL_DEV4: C17.P2(P) C18.P2(P) C19.P2(P) C20.P2(P) C21.P2(P) C22.P2(P) C23.P2(P) C24.P2(P) C25.P2(P) C26.P2(P) C27.P2(P) C28.P2(P) C29.P2(P) C30.P2(P) ; also sheet 4
DB_SEL_DEV5: C17.S2(S) C18.S2(S) C19.S2(S) C20.S2(S) C21.S2(S) C22.S2(S) C23.S2(S) C24.S2(S) C25.S2(S) C26.S2(S) C27.S2(S) C28.S2(S) C29.S2(S) C30.S2(S) ; also sheet 4
DB_SEL_DEV6: C17.U2(U) C18.U2(U) C19.U2(U) C20.U2(U) C21.U2(U) C22.U2(U) C23.U2(U) C24.U2(U) C25.U2(U) C26.U2(U) C27.U2(U) C28.U2(U) C29.U2(U) C30.U2(U) ; also sheet 4
N$79: B24.E2 B25.K2(J:I$1) C17.D2(D)
N$80: B24.F2 B25.M2(L:I$1) C18.D2(D)
N$81: B24.H2 B25.P2(N:I$1) C19.D2(D)
N$82: B24.J2 B25.S2(R:I$1) C20.D2(D)
N$83: B24.K2 B25.U2(T:I$1) C21.D2(D)
N$84: B24.L2 B26.E2(D:I$1) C22.D2(D)
N$85: B24.M2 B26.H2(F:I$1) C23.D2(D)
N$86: B24.N2 B26.K2(J:I$1) C24.D2(D)
N$87: B24.P2 B26.M2(L:I$1) C25.D2(D)
N$88: B24.R2 B26.P2(N:I$1) C26.D2(D)
N$89: B24.S2 B26.S2(R:I$1) C27.D2(D)
N$90: B24.T2 B26.U2(T:I$1) C28.D2(D)
N$91: B24.U2 B32.P2(N:I$1) C29.D2(D)
N$92: B24.V2 B32.S2(R:I$1) C30.D2(D)
Unconnected: B25.V2(T:I$2) B26.V2(T:I$2) B32.V2(T:I$2)

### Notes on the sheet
- Data Multiplexer, Data Bits
- D-BS-DM01-0-3 | D

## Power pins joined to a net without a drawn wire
-15V: A12.B2(-15V) A13.B2(-15V) A14.B2(-15V) A15.B2(-15V) A16.B2(-15V) A17.B2(-15V) A18.B2(-15V) A19.B2(-15V) A22.B2 B01.B2 B02.B2(-15V) B03.B2(-15V) B04.B2(-15V) B05.B2(-15V) B06.B2(-15V) B07.B2(-15V) B08.B2(-15V) B09.B2(-15V) B10.B2(-15V) B11.B2(-15V) B12.B2(-15V) B13.B2(-15V) B14.B2(-15V) B15.B2(-15V) B16.B2(-15V) B17.B2(-15V) B18.B2(-15V) B19.B2(-15V) B20.B2(-15V) B21.B2(-15V) B22.B2(-15V) B23.B2(-15V) B24.B2(-15V) B25.B2(-15V) B26.B2(-15V) B27.B2(-15V) B28.B2(-15V) B29.B2(-15V) B30.B2(-15V) B31.B2(-15V) B32.B2(-15V) C01.B2(-15V) C02.B2(-15V) C03.B2(-15V) C04.B2(-15V) C05.B2(-15V) C06.B2(-15V) C07.B2(-15V) C08.B2(-15V) C09.B2(-15V) C10.B2(-15V) C11.B2(-15V) C12.B2(-15V) C13.B2(-15V) C14.B2(-15V) C15.B2(-15V) C16.B2(-15V) C17.B2(-15V) C18.B2(-15V) C19.B2(-15V) C20.B2(-15V) C21.B2(-15V) C22.B2(-15V) C23.B2(-15V) C24.B2(-15V) C25.B2(-15V) C26.B2(-15V) C27.B2(-15V) C28.B2(-15V) C29.B2(-15V) C30.B2(-15V) C31.B2 C32.B2(-15V) D32.B2
GND: A01.C2 A01.F2 A01.J2 A01.L2 A01.N2 A01.R2 A01.U2 A02.C2 A02.F2 A02.J2 A02.L2 A02.N2 A02.R2 A02.U2 A03.C2 A03.F2 A03.J2 A03.L2 A03.N2 A03.R2 A03.U2 A04.C2 A04.F2 A04.J2 A04.L2 A04.N2 A04.R2 A04.U2 A05.C2 A05.F2 A05.J2 A05.L2 A05.N2 A05.R2 A05.U2 A06.C2 A06.F2 A06.J2 A06.L2 A06.N2 A06.R2 A06.U2 A07.C2 A07.F2 A07.J2 A07.L2 A07.N2 A07.R2 A07.U2 A08.C2 A08.F2 A08.J2 A08.L2 A08.N2 A08.R2 A08.U2 A09.C2 A09.F2 A09.J2 A09.L2 A09.N2 A09.R2 A09.U2 A10.C2 A10.F2 A10.J2 A10.L2 A10.N2 A10.R2 A10.U2 A11.C2 A11.F2 A11.J2 A11.L2 A11.N2 A11.R2 A11.U2 A12.C2(GND) A13.C2(GND) A14.C2(GND) A15.C2(GND) A16.C2(GND) A17.C2(GND) A18.C2(GND) A19.C2(GND) A20.C2 A20.F2 A20.J2 A20.L2 A20.N2 A20.R2 A20.U2 A21.C2 A21.F2 A21.J2 A21.L2 A21.N2 A21.R2 A21.U2 A22.C2 A23.C2 A23.F2 A23.J2 A23.L2 A23.N2 A23.R2 A23.U2 A24.C2 A24.F2 A24.J2 A24.L2 A24.N2 A24.R2 A24.U2 A25.C2 A25.F2 A25.J2 A25.L2 A25.N2 A25.R2 A25.U2 A26.C2 A26.F2 A26.J2 A26.L2 A26.N2 A26.R2 A26.U2 A27.C2 A27.F2 A27.J2 A27.L2 A27.N2 A27.R2 A27.U2 A28.C2 A28.F2 A28.J2 A28.L2 A28.N2 A28.R2 A28.U2 A29.C2 A29.F2 A29.J2 A29.L2 A29.N2 A29.R2 A29.U2 A30.C2 A30.F2 A30.J2 A30.L2 A30.N2 A30.R2 A30.U2 A31.C2 A31.F2 A31.J2 A31.L2 A31.N2 A31.R2 A31.U2 A32.C2 A32.F2 A32.J2 A32.L2 A32.N2 A32.R2 A32.U2 B01.C2 B02.C2(GND) B03.C2(GND) B04.C2(GND) B05.C2(GND) B06.C2(GND) B07.C2(GND) B08.C2(GND) B09.C2(GND) B10.C2(GND) B11.C2(GND) B12.C2(GND) B13.C2(GND) B14.C2(GND) B15.C2(GND) B16.C2(GND) B17.C2(GND) B18.C2(GND) B19.C2(GND) B20.C2(GND) B21.C2(GND) B22.C2(GND) B23.C2(GND) B24.C2(GND) B25.C2(GND) B26.C2(GND) B27.C2(GND) B28.C2(GND) B29.C2(GND) B30.C2(GND) B31.C2(GND) B32.C2(GND) C01.C2(GND) C02.C2(GND) C03.C2(GND) C04.C2(GND) C05.C2(GND) C06.C2(GND) C07.C2(GND) C08.C2(GND) C09.C2(GND) C10.C2(GND) C11.C2(GND) C12.C2(GND) C13.C2(GND) C14.C2(GND) C15.C2(GND) C16.C2(GND) C17.C2(GND) C18.C2(GND) C19.C2(GND) C20.C2(GND) C21.C2(GND) C22.C2(GND) C23.C2(GND) C24.C2(GND) C25.C2(GND) C26.C2(GND) C27.C2(GND) C28.C2(GND) C29.C2(GND) C30.C2(GND) C31.C2 C32.C2(GND) D01.C2 D01.F2 D01.J2 D01.L2 D01.N2 D01.R2 D01.U2 D02.C2 D02.F2 D02.J2 D02.L2 D02.N2 D02.R2 D02.U2 D03.C2 D03.F2 D03.J2 D03.L2 D03.N2 D03.R2 D03.U2 D04.C2 D04.F2 D04.J2 D04.L2 D04.N2 D04.R2 D04.U2 D05.C2 D05.F2 D05.J2 D05.L2 D05.N2 D05.R2 D05.U2 D06.C2 D06.F2 D06.J2 D06.L2 D06.N2 D06.R2 D06.U2 D07.C2 D07.F2 D07.J2 D07.L2 D07.N2 D07.R2 D07.U2 D08.C2 D08.F2 D08.J2 D08.L2 D08.N2 D08.R2 D08.U2 D09.C2 D09.F2 D09.J2 D09.L2 D09.N2 D09.R2 D09.U2 D10.C2 D10.F2 D10.J2 D10.L2 D10.N2 D10.R2 D10.U2 D11.C2 D11.F2 D11.J2 D11.L2 D11.N2 D11.R2 D11.U2 D12.C2 D12.F2 D12.J2 D12.L2 D12.N2 D12.R2 D12.U2 D13.C2 D13.F2 D13.J2 D13.L2 D13.N2 D13.R2 D13.U2 D14.C2 D14.F2 D14.J2 D14.L2 D14.N2 D14.R2 D14.U2 D15.C2 D15.F2 D15.J2 D15.L2 D15.N2 D15.R2 D15.U2 D16.C2 D16.F2 D16.J2 D16.L2 D16.N2 D16.R2 D16.U2 D17.C2 D17.F2 D17.J2 D17.L2 D17.N2 D17.R2 D17.U2 D18.C2 D18.F2 D18.J2 D18.L2 D18.N2 D18.R2 D18.U2 D19.C2 D19.F2 D19.J2 D19.L2 D19.N2 D19.R2 D19.U2 D20.C2 D20.F2 D20.J2 D20.L2 D20.N2 D20.R2 D20.U2 D21.C2 D21.F2 D21.J2 D21.L2 D21.N2 D21.R2 D21.U2 D22.C2 D22.F2 D22.J2 D22.L2 D22.N2 D22.R2 D22.U2 D23.C2 D23.F2 D23.J2 D23.L2 D23.N2 D23.R2 D23.U2 D24.C2 D24.F2 D24.J2 D24.L2 D24.N2 D24.R2 D24.U2 D25.C2 D25.F2 D25.J2 D25.L2 D25.N2 D25.R2 D25.U2 D26.C2 D26.F2 D26.J2 D26.L2 D26.N2 D26.R2 D26.U2 D27.C2 D27.F2 D27.J2 D27.L2 D27.N2 D27.R2 D27.U2 D28.C2 D28.F2 D28.J2 D28.L2 D28.N2 D28.R2 D28.U2 D29.C2 D29.F2 D29.J2 D29.L2 D29.N2 D29.R2 D29.U2 D30.C2 D30.F2 D30.J2 D30.L2 D30.N2 D30.R2 D30.U2 D31.C2 D31.F2 D31.J2 D31.L2 D31.N2 D31.R2 D31.U2 D32.C2
VCC: A12.A2(VCC) A13.A2(VCC) A14.A2(VCC) A15.A2(VCC) A16.A2(VCC) A17.A2(VCC) A18.A2(VCC) A19.A2(VCC) A22.A2 B01.A2 B02.A2(VCC) B03.A2(VCC) B04.A2(VCC) B05.A2(VCC) B06.A2(VCC) B07.A2(VCC) B08.A2(VCC) B09.A2(VCC) B10.A2(VCC) B11.A2(VCC) B12.A2(VCC) B13.A2(VCC) B14.A2(VCC) B15.A2(VCC) B16.A2(VCC) B17.A2(VCC) B18.A2(VCC) B19.A2(VCC) B20.A2(VCC) B21.A2(VCC) B22.A2(VCC) B23.A2(VCC) B24.A2(VCC) B25.A2(VCC) B26.A2(VCC) B27.A2(VCC) B28.A2(VCC) B29.A2(VCC) B30.A2(VCC) B31.A2(VCC) B32.A2(VCC) C01.A2(VCC) C02.A2(VCC) C03.A2(VCC) C04.A2(VCC) C05.A2(VCC) C06.A2(VCC) C07.A2(VCC) C08.A2(VCC) C09.A2(VCC) C10.A2(VCC) C11.A2(VCC) C12.A2(VCC) C13.A2(VCC) C14.A2(VCC) C15.A2(VCC) C16.A2(VCC) C17.A2(VCC) C18.A2(VCC) C19.A2(VCC) C20.A2(VCC) C21.A2(VCC) C22.A2(VCC) C23.A2(VCC) C24.A2(VCC) C25.A2(VCC) C26.A2(VCC) C27.A2(VCC) C28.A2(VCC) C29.A2(VCC) C30.A2(VCC) C31.A2 C32.A2(VCC) D32.A2

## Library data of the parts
A01-A09 A10 A11 A20 A21 A23-A32 D01-D09 D10-D31 = dec-r:W021: One-sided 9 pin connector/cable with grounds (Negibus).
A12 A13 B02 B04 B05 B07 B10 B13 B15 B25 B26 B32 = dec-r:R107: 7 Inverters
A14 A15 B27-B29 = dec-r:W640: Pulse Amplifiers
A16-A18 B06 B08 B23 B30 B31 = dec-r:R111: Diode Gate
A19 B14 B16-B21 = dec-r:R202: Dual Flip-Flop
A22 B01 C31 D32 = dec-r:EMPTY: Empty Slot
B03 = dec-r:R603: Triple Pulse Amplifier
B09 B11 B24 = dec-r:W005: 15 Clamped Loads
B12 = dec-r:R181: Carry Chain/Priority Encoder
B22 = dec-r:R002: 5 Diode Networks
C01-C09 C10-C30 = dec-r:R141: AND/NOR Gate
C32 = dec-r:R302: Dual Delay (One Shot)
PDP-12/8I/8 = jumper:JP3Q: JUMPER

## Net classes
1 Supply: width 0.508 mm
